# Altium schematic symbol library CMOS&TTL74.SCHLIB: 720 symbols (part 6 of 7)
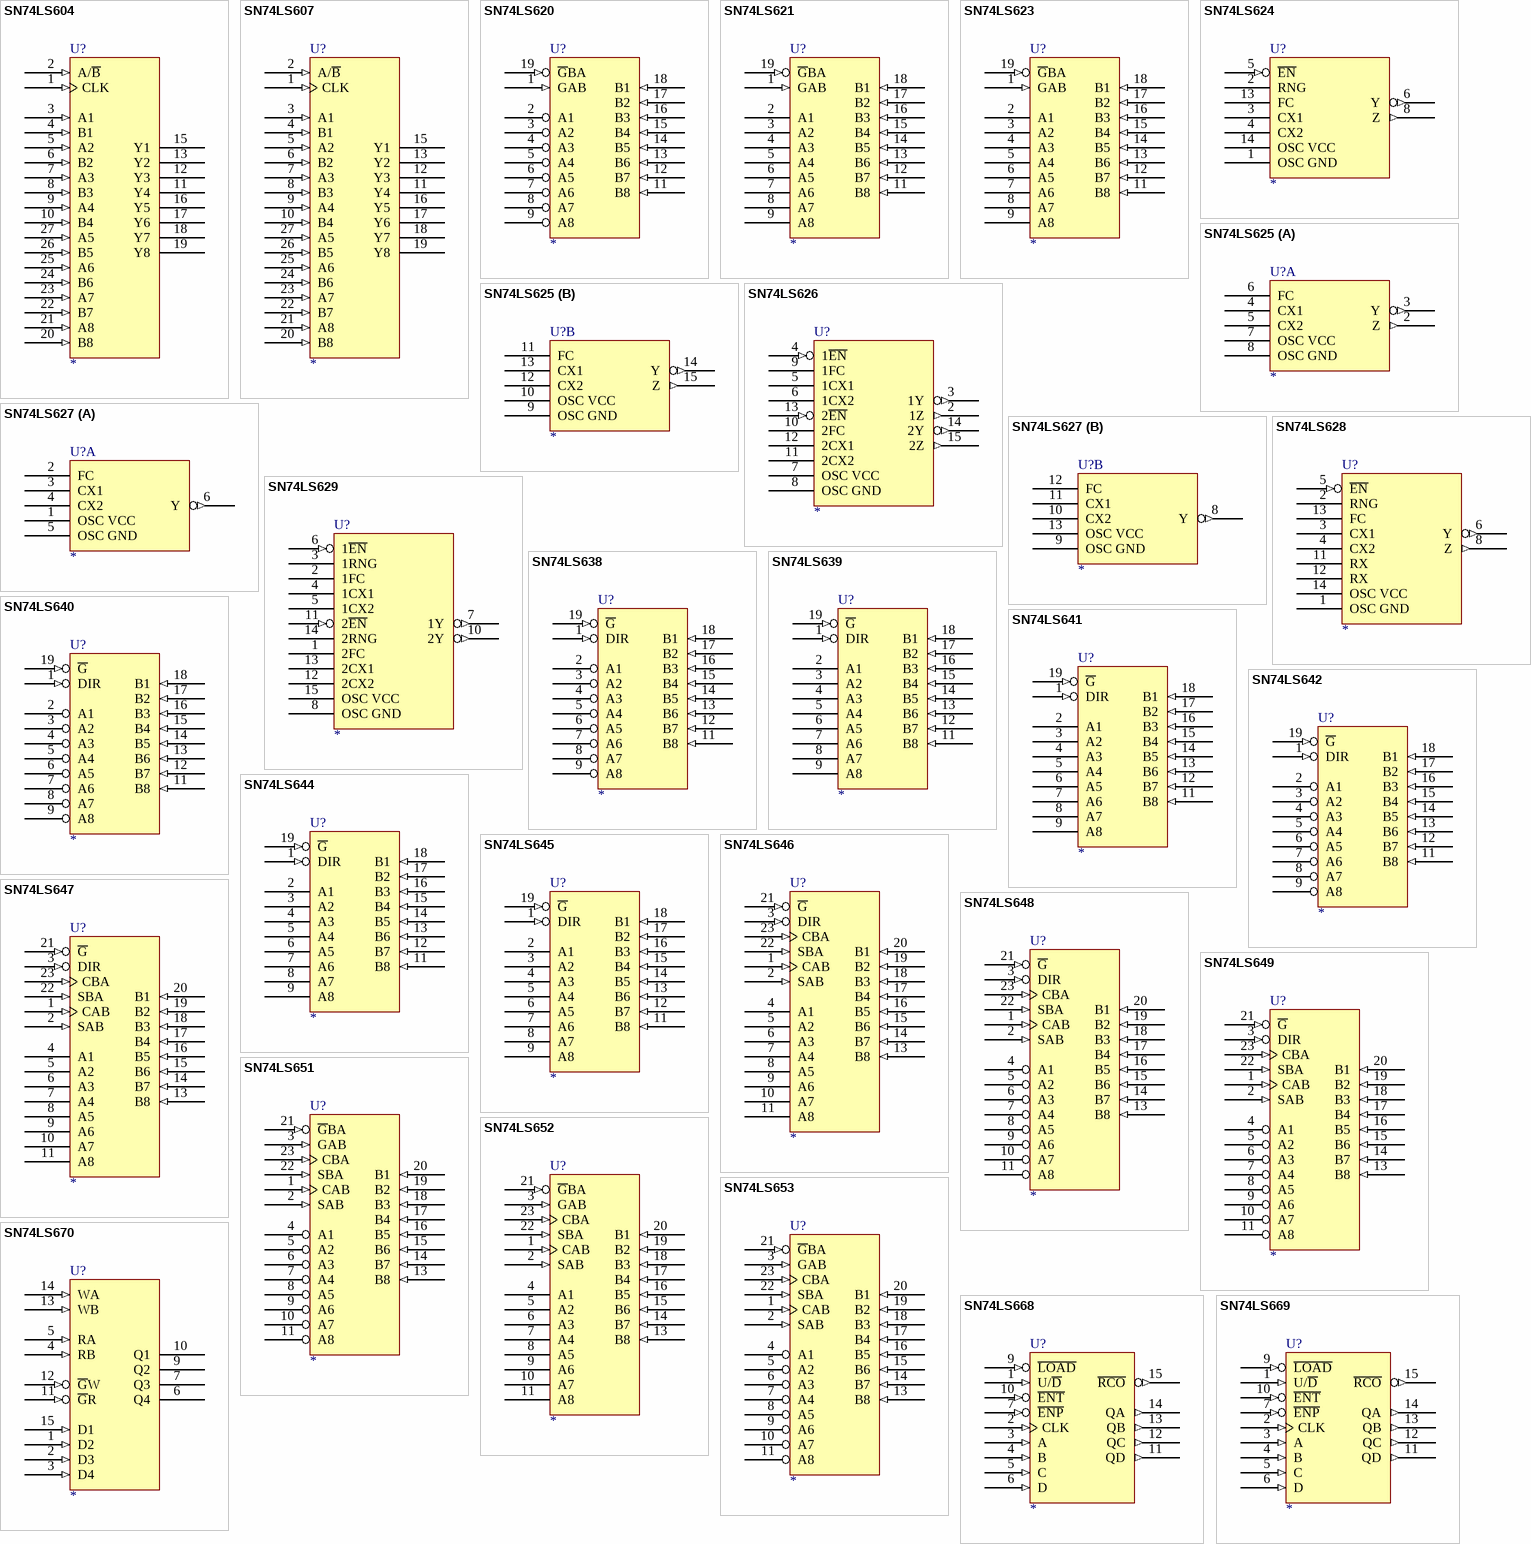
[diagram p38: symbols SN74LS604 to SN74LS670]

## SN74LS629
designator U?
VOLTAGE-CONTROLLED OSC
footprint SO16
footprint DIP-16
pins: 1 2FC, 2 1FC, 3 1RNG, 4 1CX1, 5 1CX2, 6 1~{EN} (in), 7 1Y (out), 8 OSC GND (power), 9 GND (power) hidden to GND, 10 2Y (out), 11 2~{EN} (in), 12 2CX2, 13 2CX1, 14 2RNG, 15 OSC VCC (power), 16 VCC (power) hidden to VCC
1 alternate drawing of the same symbol

## SN74LS638
designator U?
OCTAL BUS TRANCEIVER
footprint DIP-20
footprint SO20W
pins: 1 DIR (in), 2 A1 (oc), 3 A2 (oc), 4 A3 (oc), 5 A4 (oc), 6 A5 (oc), 7 A6 (oc), 8 A7 (oc), 9 A8 (oc), 10 GND (power) hidden to GND, 11 B8 (in), 12 B7 (in), 13 B6 (in), 14 B5 (in), 15 B4 (in), 16 B3 (in), 17 B2 (in), 18 B1 (in), 19 ~{G} (in), 20 VCC (power) hidden to VCC
1 alternate drawing of the same symbol

## SN74LS639
designator U?
OCTAL BUS TRANCEIVER
footprint DIP-20
footprint SO20W
pins: 1 DIR (in), 2 A1 (oc), 3 A2 (oc), 4 A3 (oc), 5 A4 (oc), 6 A5 (oc), 7 A6 (oc), 8 A7 (oc), 9 A8 (oc), 10 GND (power) hidden to GND, 11 B8 (in), 12 B7 (in), 13 B6 (in), 14 B5 (in), 15 B4 (in), 16 B3 (in), 17 B2 (in), 18 B1 (in), 19 ~{G} (in), 20 VCC (power) hidden to VCC
1 alternate drawing of the same symbol

## SN74LS640
designator U?
OCTAL BUS TRANCEIVER
footprint SO20W
footprint DIP-20
pins: 1 DIR (in), 2 A1 (hiz), 3 A2 (hiz), 4 A3 (hiz), 5 A4 (hiz), 6 A5 (hiz), 7 A6 (hiz), 8 A7 (hiz), 9 A8 (hiz), 10 GND (power) hidden to GND, 11 B8 (in), 12 B7 (in), 13 B6 (in), 14 B5 (in), 15 B4 (in), 16 B3 (in), 17 B2 (in), 18 B1 (in), 19 ~{G} (in), 20 VCC (power) hidden to VCC
1 alternate drawing of the same symbol

## SN74LS641
designator U?
OCTAL BUS TRANCEIVER
footprint DIP-20
footprint SO20W
pins: 1 DIR (in), 2 A1 (oc), 3 A2 (oc), 4 A3 (oc), 5 A4 (oc), 6 A5 (oc), 7 A6 (oc), 8 A7 (oc), 9 A8 (oc), 10 GND (power) hidden to GND, 11 B8 (in), 12 B7 (in), 13 B6 (in), 14 B5 (in), 15 B4 (in), 16 B3 (in), 17 B2 (in), 18 B1 (in), 19 ~{G} (in), 20 VCC (power) hidden to VCC
1 alternate drawing of the same symbol

## SN74LS642
designator U?
OCTAL BUS TRANCEIVER
footprint DIP-20
footprint SO20W
pins: 1 DIR (in), 2 A1 (oc), 3 A2 (oc), 4 A3 (oc), 5 A4 (oc), 6 A5 (oc), 7 A6 (oc), 8 A7 (oc), 9 A8 (oc), 10 GND (power) hidden to GND, 11 B8 (in), 12 B7 (in), 13 B6 (in), 14 B5 (in), 15 B4 (in), 16 B3 (in), 17 B2 (in), 18 B1 (in), 19 ~{G} (in), 20 VCC (power) hidden to VCC
1 alternate drawing of the same symbol

## SN74LS644
designator U?
OCTAL BUS TRANCEIVER
footprint DIP-20
footprint SO20W
pins: 1 DIR (in), 2 A1 (oc), 3 A2 (oc), 4 A3 (oc), 5 A4 (oc), 6 A5 (oc), 7 A6 (oc), 8 A7 (oc), 9 A8 (oc), 10 GND (power) hidden to GND, 11 B8 (in), 12 B7 (in), 13 B6 (in), 14 B5 (in), 15 B4 (in), 16 B3 (in), 17 B2 (in), 18 B1 (in), 19 ~{G} (in), 20 VCC (power) hidden to VCC
1 alternate drawing of the same symbol

## SN74LS645
designator U?
OCTAL BUS TRANCEIVER
footprint DIP-20
footprint SO20W
pins: 1 DIR (in), 2 A1 (hiz), 3 A2 (hiz), 4 A3 (hiz), 5 A4 (hiz), 6 A5 (hiz), 7 A6 (hiz), 8 A7 (hiz), 9 A8 (hiz), 10 GND (power) hidden to GND, 11 B8 (in), 12 B7 (in), 13 B6 (in), 14 B5 (in), 15 B4 (in), 16 B3 (in), 17 B2 (in), 18 B1 (in), 19 ~{G} (in), 20 VCC (power) hidden to VCC
1 alternate drawing of the same symbol

## SN74LS646
designator U?
OCTAL BUS TRANCEIVER AND REG
footprint DIP-24
footprint SO24W
pins: 1 CAB (in), 2 SAB (in), 3 DIR (in), 4 A1 (hiz), 5 A2 (hiz), 6 A3 (hiz), 7 A4 (hiz), 8 A5 (hiz), 9 A6 (hiz), 10 A7 (hiz), 11 A8 (hiz), 12 GND (power) hidden to GND, 13 B8 (in), 14 B7 (in), 15 B6 (in), 16 B5 (in), 17 B4 (in), 18 B3 (in), 19 B2 (in), 20 B1 (in), 21 ~{G} (in), 22 SBA (in), 23 CBA (in), 24 VCC (power) hidden to VCC
1 alternate drawing of the same symbol

## SN74LS647
designator U?
OCTAL BUS TRANCEIVER AND REG
footprint DIP-24
footprint SO24W
pins: 1 CAB (in), 2 SAB (in), 3 DIR (in), 4 A1 (oc), 5 A2 (oc), 6 A3 (oc), 7 A4 (oc), 8 A5 (oc), 9 A6 (oc), 10 A7 (oc), 11 A8 (oc), 12 GND (power) hidden to GND, 13 B8 (in), 14 B7 (in), 15 B6 (in), 16 B5 (in), 17 B4 (in), 18 B3 (in), 19 B2 (in), 20 B1 (in), 21 ~{G} (in), 22 SBA (in), 23 CBA (in), 24 VCC (power) hidden to VCC
1 alternate drawing of the same symbol

## SN74LS648
designator U?
OCTAL BUS TRANCEIVER AND REG
footprint DIP-24
footprint SO24W
pins: 1 CAB (in), 2 SAB (in), 3 DIR (in), 4 A1 (hiz), 5 A2 (hiz), 6 A3 (hiz), 7 A4 (hiz), 8 A5 (hiz), 9 A6 (hiz), 10 A7 (hiz), 11 A8 (hiz), 12 GND (power) hidden to GND, 13 B8 (in), 14 B7 (in), 15 B6 (in), 16 B5 (in), 17 B4 (in), 18 B3 (in), 19 B2 (in), 20 B1 (in), 21 ~{G} (in), 22 SBA (in), 23 CBA (in), 24 VCC (power) hidden to VCC
1 alternate drawing of the same symbol

## SN74LS649
designator U?
OCTAL BUS TRANCEIVER AND REG
footprint SO24W
footprint DIP-24
pins: 1 CAB (in), 2 SAB (in), 3 DIR (in), 4 A1 (oc), 5 A2 (oc), 6 A3 (oc), 7 A4 (oc), 8 A5 (oc), 9 A6 (oc), 10 A7 (oc), 11 A8 (oc), 12 GND (power) hidden to GND, 13 B8 (in), 14 B7 (in), 15 B6 (in), 16 B5 (in), 17 B4 (in), 18 B3 (in), 19 B2 (in), 20 B1 (in), 21 ~{G} (in), 22 SBA (in), 23 CBA (in), 24 VCC (power) hidden to VCC
1 alternate drawing of the same symbol

## SN74LS651
designator U?
OCTAL BUS TRANCEIVER AND REG
footprint DIP-24
footprint SO24W
pins: 1 CAB (in), 2 SAB (in), 3 GAB (in), 4 A1 (hiz), 5 A2 (hiz), 6 A3 (hiz), 7 A4 (hiz), 8 A5 (hiz), 9 A6 (hiz), 10 A7 (hiz), 11 A8 (hiz), 12 GND (power) hidden to GND, 13 B8 (in), 14 B7 (in), 15 B6 (in), 16 B5 (in), 17 B4 (in), 18 B3 (in), 19 B2 (in), 20 B1 (in), 21 ~{G}BA (in), 22 SBA (in), 23 CBA (in), 24 VCC (power) hidden to VCC
1 alternate drawing of the same symbol

## SN74LS652
designator U?
OCTAL BUS TRANCEIVER AND REG
footprint SO24W
footprint DIP-24
pins: 1 CAB (in), 2 SAB (in), 3 GAB (in), 4 A1 (hiz), 5 A2 (hiz), 6 A3 (hiz), 7 A4 (hiz), 8 A5 (hiz), 9 A6 (hiz), 10 A7 (hiz), 11 A8 (hiz), 12 GND (power) hidden to GND, 13 B8 (in), 14 B7 (in), 15 B6 (in), 16 B5 (in), 17 B4 (in), 18 B3 (in), 19 B2 (in), 20 B1 (in), 21 ~{G}BA (in), 22 SBA (in), 23 CBA (in), 24 VCC (power) hidden to VCC
1 alternate drawing of the same symbol

## SN74LS653
designator U?
OCTAL BUS TRANCEIVER AND REG
footprint DIP-24
footprint SO24W
pins: 1 CAB (in), 2 SAB (in), 3 GAB (in), 4 A1 (oc), 5 A2 (oc), 6 A3 (oc), 7 A4 (oc), 8 A5 (oc), 9 A6 (oc), 10 A7 (oc), 11 A8 (oc), 12 GND (power) hidden to GND, 13 B8 (in), 14 B7 (in), 15 B6 (in), 16 B5 (in), 17 B4 (in), 18 B3 (in), 19 B2 (in), 20 B1 (in), 21 ~{G}BA (in), 22 SBA (in), 23 CBA (in), 24 VCC (power) hidden to VCC
1 alternate drawing of the same symbol

## SN74LS668
designator U?
SYNCHRONOUS 4-BIT UP/DOWN CNT
footprint DIP-16
footprint SO16
pins: 1 U/~{D} (in), 2 CLK (in), 3 A (in), 4 B (in), 5 C (in), 6 D (in), 7 ~{ENP} (in), 8 GND (power) hidden to GND, 9 ~{LOAD} (in), 10 ~{ENT} (in), 11 QD (out), 12 QC (out), 13 QB (out), 14 QA (out), 15 ~{RCO} (out), 16 VCC (power) hidden to VCC
1 alternate drawing of the same symbol

## SN74LS669
designator U?
SYNCHRONOUS 4-BIT UP/DOWN CNT
footprint DIP-16
footprint SO16
pins: 1 U/~{D} (in), 2 CLK (in), 3 A (in), 4 B (in), 5 C (in), 6 D (in), 7 ~{ENP} (in), 8 GND (power) hidden to GND, 9 ~{LOAD} (in), 10 ~{ENT} (in), 11 QD (out), 12 QC (out), 13 QB (out), 14 QA (out), 15 ~{RCO} (out), 16 VCC (power) hidden to VCC
1 alternate drawing of the same symbol

## SN74LS670
designator U?
4-BY-4 REG FILES 3SO
footprint SO16
footprint DIP-16
pins: 1 D2 (in), 2 D3 (in), 3 D4 (in), 4 RB (in), 5 RA (in), 6 Q4 (hiz), 7 Q3 (hiz), 8 GND (power) hidden to GND, 9 Q2 (hiz), 10 Q1 (hiz), 11 ~{G}R (in), 12 ~{G}W (in), 13 WB (in), 14 WA (in), 15 D1 (in), 16 VCC (power) hidden to VCC
1 alternate drawing of the same symbol

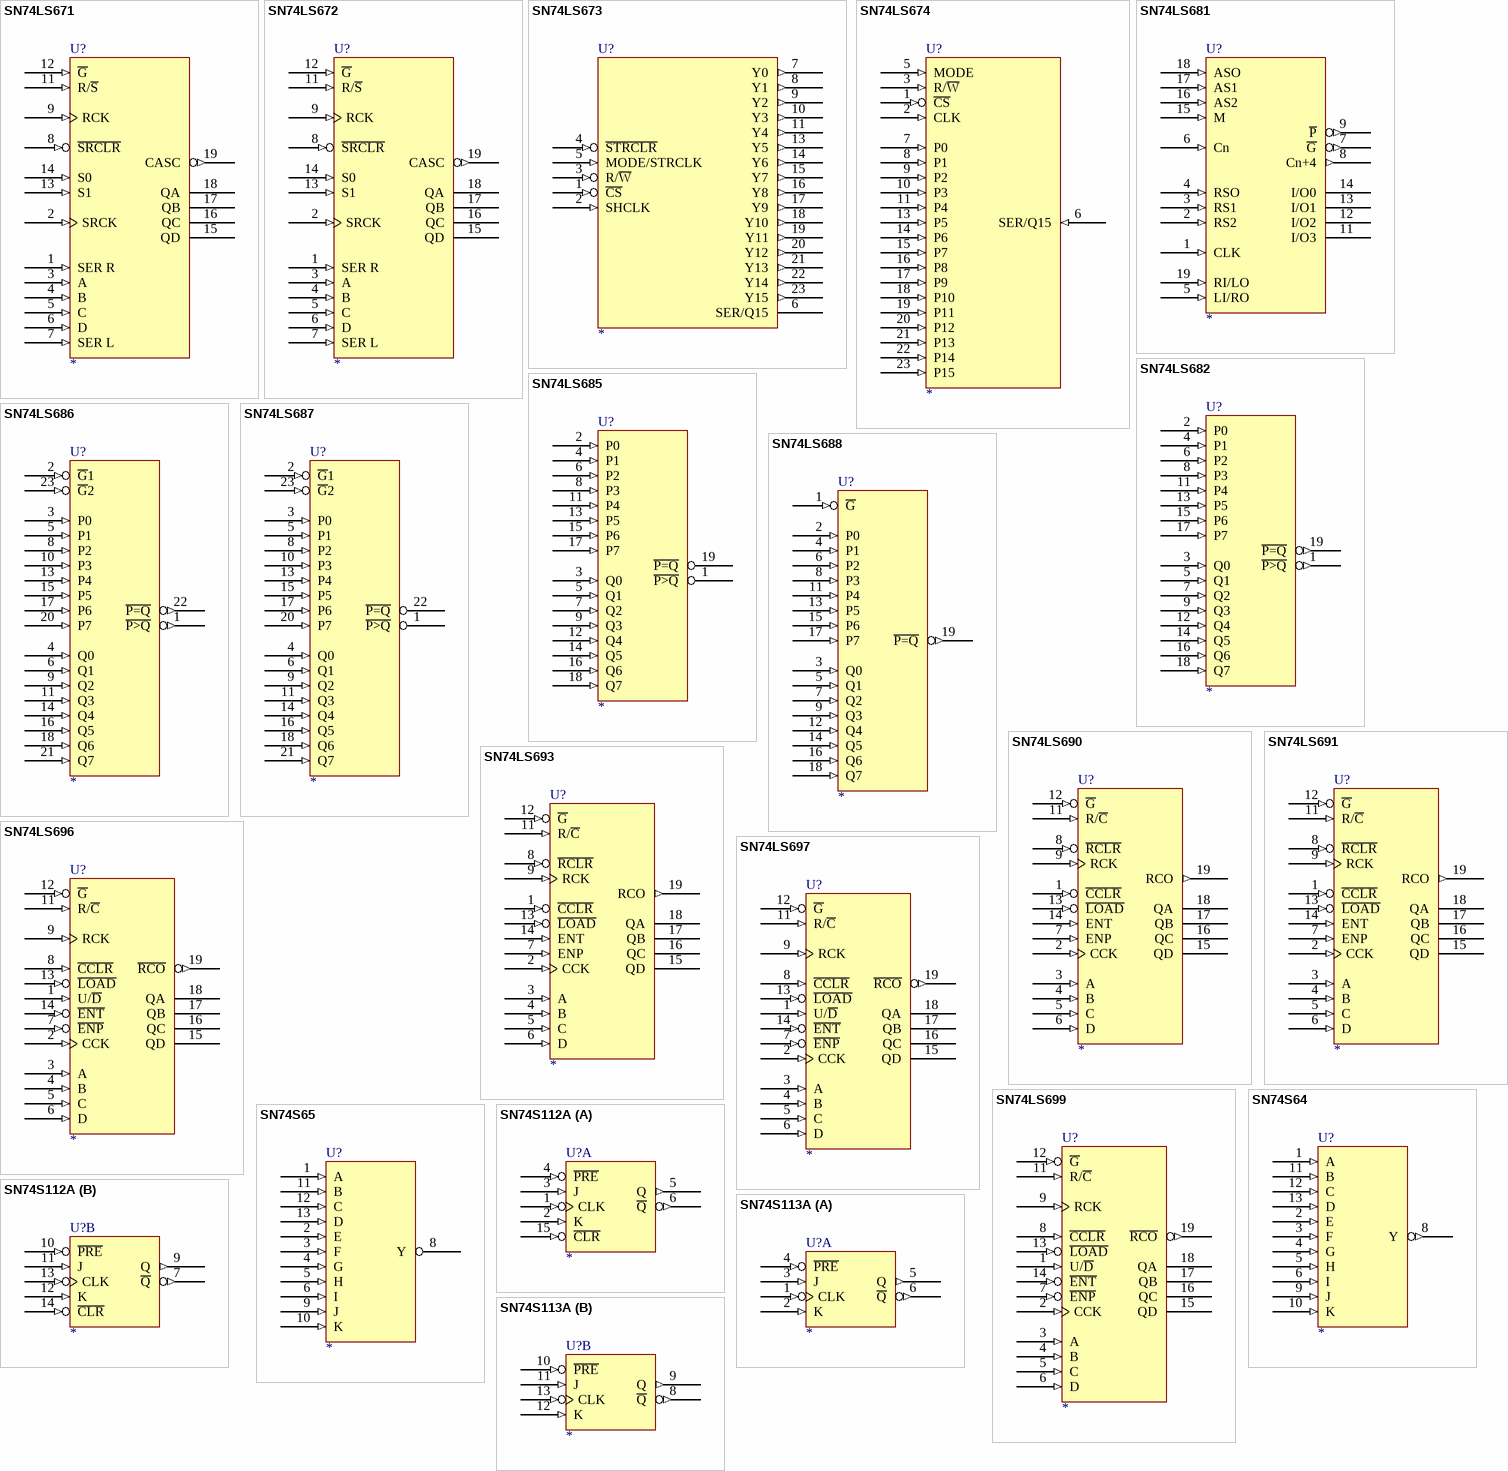
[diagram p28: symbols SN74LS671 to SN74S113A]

## SN74LS671
designator U?
4-BIT UNIVERSAL SFT REG/LCH 3SO
footprint SO20W
footprint DIP-20
pins: 1 SER R (in), 2 SRCK (in), 3 A (in), 4 B (in), 5 C (in), 6 D (in), 7 SER L (in), 8 ~{SRCLR} (in), 9 RCK (in), 10 GND (power) hidden to GND, 11 R/~{S} (in), 12 ~{G} (in), 13 S1 (in), 14 S0 (in), 15 QD (hiz), 16 QC (hiz), 17 QB (hiz), 18 QA (hiz), 19 CASC (out), 20 VCC (power) hidden to VCC
1 alternate drawing of the same symbol

## SN74LS672
designator U?
4-BIT UNIVERSAL SFT REG/LCH 3SO
footprint SO20W
footprint DIP-20
pins: 1 SER R (in), 2 SRCK (in), 3 A (in), 4 B (in), 5 C (in), 6 D (in), 7 SER L (in), 8 ~{SRCLR} (in), 9 RCK (in), 10 GND (power) hidden to GND, 11 R/~{S} (in), 12 ~{G} (in), 13 S1 (in), 14 S0 (in), 15 QD (hiz), 16 QC (hiz), 17 QB (hiz), 18 QA (hiz), 19 CASC (out), 20 VCC (power) hidden to VCC
1 alternate drawing of the same symbol

## SN74LS673
designator U?
16-BIT SFT REG
footprint SO24W
footprint DIP-24
pins: 1 ~{CS} (in), 2 SHCLK (in), 3 R/~{W} (in), 4 ~{STRCLR} (in), 5 MODE/STRCLK (in), 6 SER/Q15 (hiz), 7 Y0 (out), 8 Y1 (out), 9 Y2 (out), 10 Y3 (out), 11 Y4 (out), 12 GND (power) hidden to GND, 13 Y5 (out), 14 Y6 (out), 15 Y7 (out), 16 Y8 (out), 17 Y9 (out), 18 Y10 (out), 19 Y11 (out), 20 Y12 (out), 21 Y13 (out), 22 Y14 (out), 23 Y15 (out), 24 VCC (power) hidden to VCC
1 alternate drawing of the same symbol

## SN74LS674
designator U?
16-BIT SFT REG
footprint SO24W
footprint DIP-24
pins: 1 ~{CS} (in), 2 CLK (in), 3 R/~{W} (in), 5 MODE (in), 6 SER/Q15 (in), 7 P0 (in), 8 P1 (in), 9 P2 (in), 10 P3 (in), 11 P4 (in), 12 GND (power) hidden to GND, 13 P5 (in), 14 P6 (in), 15 P7 (in), 16 P8 (in), 17 P9 (in), 18 P10 (in), 19 P11 (in), 20 P12 (in), 21 P13 (in), 22 P14 (in), 23 P15 (in), 24 VCC (power) hidden to VCC
1 alternate drawing of the same symbol

## SN74LS681
designator U?
4-BIT PARALLEL BIN ACCUMULATOR
footprint DIP-20
footprint SO20W
pins: 1 CLK (in), 2 RS2 (in), 3 RS1 (in), 4 RSO (in), 5 LI/RO (in), 6 Cn (in), 7 ~{G} (out), 8 Cn+4 (out), 9 ~{P} (out), 10 GND (power) hidden to GND, 11 I/O3 (hiz), 12 I/O2 (hiz), 13 I/O1 (hiz), 14 I/O0 (hiz), 15 M (in), 16 AS2 (in), 17 AS1 (in), 18 ASO (in), 19 RI/LO (in), 20 VCC (power) hidden to VCC
1 alternate drawing of the same symbol

## SN74LS682
designator U?
8-BIT MAGNITUDE/IDENTITY COMPARATOR
footprint DIP-20
footprint SO20W
pins: 1 ~{P>Q} (out), 2 P0 (in), 3 Q0 (in), 4 P1 (in), 5 Q1 (in), 6 P2 (in), 7 Q2 (in), 8 P3 (in), 9 Q3 (in), 10 GND (power) hidden to GND, 11 P4 (in), 12 Q4 (in), 13 P5 (in), 14 Q5 (in), 15 P6 (in), 16 Q6 (in), 17 P7 (in), 18 Q7 (in), 19 ~{P=Q} (out), 20 VCC (power) hidden to VCC
1 alternate drawing of the same symbol

## SN74LS685
designator U?
8-BIT MAGNITUDE/IDENTITY COMPARATOR
footprint SO20W
footprint DIP-20
pins: 1 ~{P>Q} (oc), 2 P0 (in), 3 Q0 (in), 4 P1 (in), 5 Q1 (in), 6 P2 (in), 7 Q2 (in), 8 P3 (in), 9 Q3 (in), 10 GND (power) hidden to GND, 11 P4 (in), 12 Q4 (in), 13 P5 (in), 14 Q5 (in), 15 P6 (in), 16 Q6 (in), 17 P7 (in), 18 Q7 (in), 19 ~{P=Q} (oc), 20 VCC (power) hidden to VCC
1 alternate drawing of the same symbol

## SN74LS686
designator U?
8-BIT MAGNITUDE/IDENTITY COMPARATOR
footprint DIP-24
footprint SO24W
pins: 1 ~{P>Q} (out), 2 ~{G}1 (in), 3 P0 (in), 4 Q0 (in), 5 P1 (in), 6 Q1 (in), 8 P2 (in), 9 Q2 (in), 10 P3 (in), 11 Q3 (in), 12 GND (power) hidden to GND, 13 P4 (in), 14 Q4 (in), 15 P5 (in), 16 Q5 (in), 17 P6 (in), 18 Q6 (in), 20 P7 (in), 21 Q7 (in), 22 ~{P=Q} (out), 23 ~{G}2 (in), 24 VCC (power) hidden to VCC
1 alternate drawing of the same symbol

## SN74LS687
designator U?
8-BIT MAGNITUDE/IDENTITY COMPARATOR
footprint DIP-24
footprint SO24W
pins: 1 ~{P>Q} (oc), 2 ~{G}1 (in), 3 P0 (in), 4 Q0 (in), 5 P1 (in), 6 Q1 (in), 8 P2 (in), 9 Q2 (in), 10 P3 (in), 11 Q3 (in), 12 GND (power) hidden to GND, 13 P4 (in), 14 Q4 (in), 15 P5 (in), 16 Q5 (in), 17 P6 (in), 18 Q6 (in), 20 P7 (in), 21 Q7 (in), 22 ~{P=Q} (oc), 23 ~{G}2 (in), 24 VCC (power) hidden to VCC
1 alternate drawing of the same symbol

## SN74LS688
designator U?
8-BIT MAGNITUDE/IDENTITY COMPARATOR
footprint DIP-20
footprint SO20W
pins: 1 ~{G} (in), 2 P0 (in), 3 Q0 (in), 4 P1 (in), 5 Q1 (in), 6 P2 (in), 7 Q2 (in), 8 P3 (in), 9 Q3 (in), 10 GND (power) hidden to GND, 11 P4 (in), 12 Q4 (in), 13 P5 (in), 14 Q5 (in), 15 P6 (in), 16 Q6 (in), 17 P7 (in), 18 Q7 (in), 19 ~{P=Q} (out), 20 VCC (power) hidden to VCC
1 alternate drawing of the same symbol

## SN74LS690
designator U?
SYNCHRONOUS CNT WITH OUTPUT REG AND MUX 3SO
footprint SO20W
footprint DIP-20
pins: 1 ~{CCLR} (in), 2 CCK (in), 3 A (in), 4 B (in), 5 C (in), 6 D (in), 7 ENP (in), 8 ~{RCLR} (in), 9 RCK (in), 10 GND (power) hidden to GND, 11 R/~{C} (in), 12 ~{G} (in), 13 ~{LOAD} (in), 14 ENT (in), 15 QD (hiz), 16 QC (hiz), 17 QB (hiz), 18 QA (hiz), 19 RCO (out), 20 VCC (power) hidden to VCC
1 alternate drawing of the same symbol

## SN74LS691
designator U?
SYNCHRONOUS CNT WITH OUTPUT REG AND MUX 3SO
footprint SO20W
footprint DIP-20
pins: 1 ~{CCLR} (in), 2 CCK (in), 3 A (in), 4 B (in), 5 C (in), 6 D (in), 7 ENP (in), 8 ~{RCLR} (in), 9 RCK (in), 10 GND (power) hidden to GND, 11 R/~{C} (in), 12 ~{G} (in), 13 ~{LOAD} (in), 14 ENT (in), 15 QD (hiz), 16 QC (hiz), 17 QB (hiz), 18 QA (hiz), 19 RCO (out), 20 VCC (power) hidden to VCC
1 alternate drawing of the same symbol

## SN74LS693
designator U?
SYNCHRONOUS CNT WITH OUTPUT REG AND MUX 3SO
footprint DIP-20
footprint SO20W
pins: 1 ~{CCLR} (in), 2 CCK (in), 3 A (in), 4 B (in), 5 C (in), 6 D (in), 7 ENP (in), 8 ~{RCLR} (in), 9 RCK (in), 10 GND (power) hidden to GND, 11 R/~{C} (in), 12 ~{G} (in), 13 ~{LOAD} (in), 14 ENT (in), 15 QD (hiz), 16 QC (hiz), 17 QB (hiz), 18 QA (hiz), 19 RCO (out), 20 VCC (power) hidden to VCC
1 alternate drawing of the same symbol

## SN74LS696
designator U?
SYNCHRONOUS U/D CNT WITH OUTPUT REG AND MUX 3SO
footprint DIP-20
footprint SO20W
pins: 1 U/~{D} (in), 2 CCK (in), 3 A (in), 4 B (in), 5 C (in), 6 D (in), 7 ~{ENP} (in), 8 ~{CCLR} (in), 9 RCK (in), 10 GND (power) hidden to GND, 11 R/~{C} (in), 12 ~{G} (in), 13 ~{LOAD} (in), 14 ~{ENT} (in), 15 QD (hiz), 16 QC (hiz), 17 QB (hiz), 18 QA (hiz), 19 ~{RCO} (out), 20 VCC (power) hidden to VCC
1 alternate drawing of the same symbol

## SN74LS697
designator U?
SYNCHRONOUS U/D CNT WITH OUTPUT REG AND MUX 3SO
footprint DIP-20
footprint SO20W
pins: 1 U/~{D} (in), 2 CCK (in), 3 A (in), 4 B (in), 5 C (in), 6 D (in), 7 ~{ENP} (in), 8 ~{CCLR} (in), 9 RCK (in), 10 GND (power) hidden to GND, 11 R/~{C} (in), 12 ~{G} (in), 13 ~{LOAD} (in), 14 ~{ENT} (in), 15 QD (hiz), 16 QC (hiz), 17 QB (hiz), 18 QA (hiz), 19 ~{RCO} (out), 20 VCC (power) hidden to VCC
1 alternate drawing of the same symbol

## SN74LS699
designator U?
SYNCHRONOUS U/D CNT WITH OUTPUT REG AND MUX 3SO
footprint DIP-20
footprint SO20W
pins: 1 U/~{D} (in), 2 CCK (in), 3 A (in), 4 B (in), 5 C (in), 6 D (in), 7 ~{ENP} (in), 8 ~{CCLR} (in), 9 RCK (in), 10 GND (power) hidden to GND, 11 R/~{C} (in), 12 ~{G} (in), 13 ~{LOAD} (in), 14 ~{ENT} (in), 15 QD (hiz), 16 QC (hiz), 17 QB (hiz), 18 QA (hiz), 19 ~{RCO} (out), 20 VCC (power) hidden to VCC
1 alternate drawing of the same symbol

## SN74S64
designator U?
4-2-3-2 IN AND-OR-INVERT G
footprint SO14
footprint DIP-14
pins: 1 A (in), 2 E (in), 3 F (in), 4 G (in), 5 H (in), 6 I (in), 7 GND (power) hidden to GND, 8 Y (out), 9 J (in), 10 K (in), 11 B (in), 12 C (in), 13 D (in), 14 VCC (power) hidden to VCC
1 alternate drawing of the same symbol

## SN74S65
designator U?
4-2-3-2 IN AND-OR-INVERT G
footprint SO14
footprint DIP-14
pins: 1 A (in), 2 E (in), 3 F (in), 4 G (in), 5 H (in), 6 I (in), 7 GND (power) hidden to GND, 8 Y (oc), 9 J (in), 10 K (in), 11 B (in), 12 C (in), 13 D (in), 14 VCC (power) hidden to VCC
1 alternate drawing of the same symbol

## SN74S112A
designator U?
DUAL J-K NET FF RS CR
footprint SO16
footprint DIP-16
part A pins: 1 CLK (in), 2 K (in), 3 J (in), 4 ~{PRE} (in), 5 Q (out), 6 ~{Q} (out), 8 GND (power) hidden to GND, 15 ~{CLR} (in), 16 VCC (power) hidden to VCC
part B pins: 7 ~{Q} (out), 8 GND (power) hidden to GND, 9 Q (out), 10 ~{PRE} (in), 11 J (in), 12 K (in), 13 CLK (in), 14 ~{CLR} (in), 16 VCC (power) hidden to VCC
1 alternate drawing of the same symbol

## SN74S113A
designator U?
DUAL J-K NET FF RS
footprint SO14
footprint DIP-14
part A pins: 1 CLK (in), 2 K (in), 3 J (in), 4 ~{PRE} (in), 5 Q (out), 6 ~{Q} (out), 7 GND (power) hidden to GND, 14 VCC (power) hidden to VCC
part B pins: 7 GND (power) hidden to GND, 8 ~{Q} (out), 9 Q (out), 10 ~{PRE} (in), 11 J (in), 12 K (in), 13 CLK (in), 14 VCC (power) hidden to VCC
1 alternate drawing of the same symbol

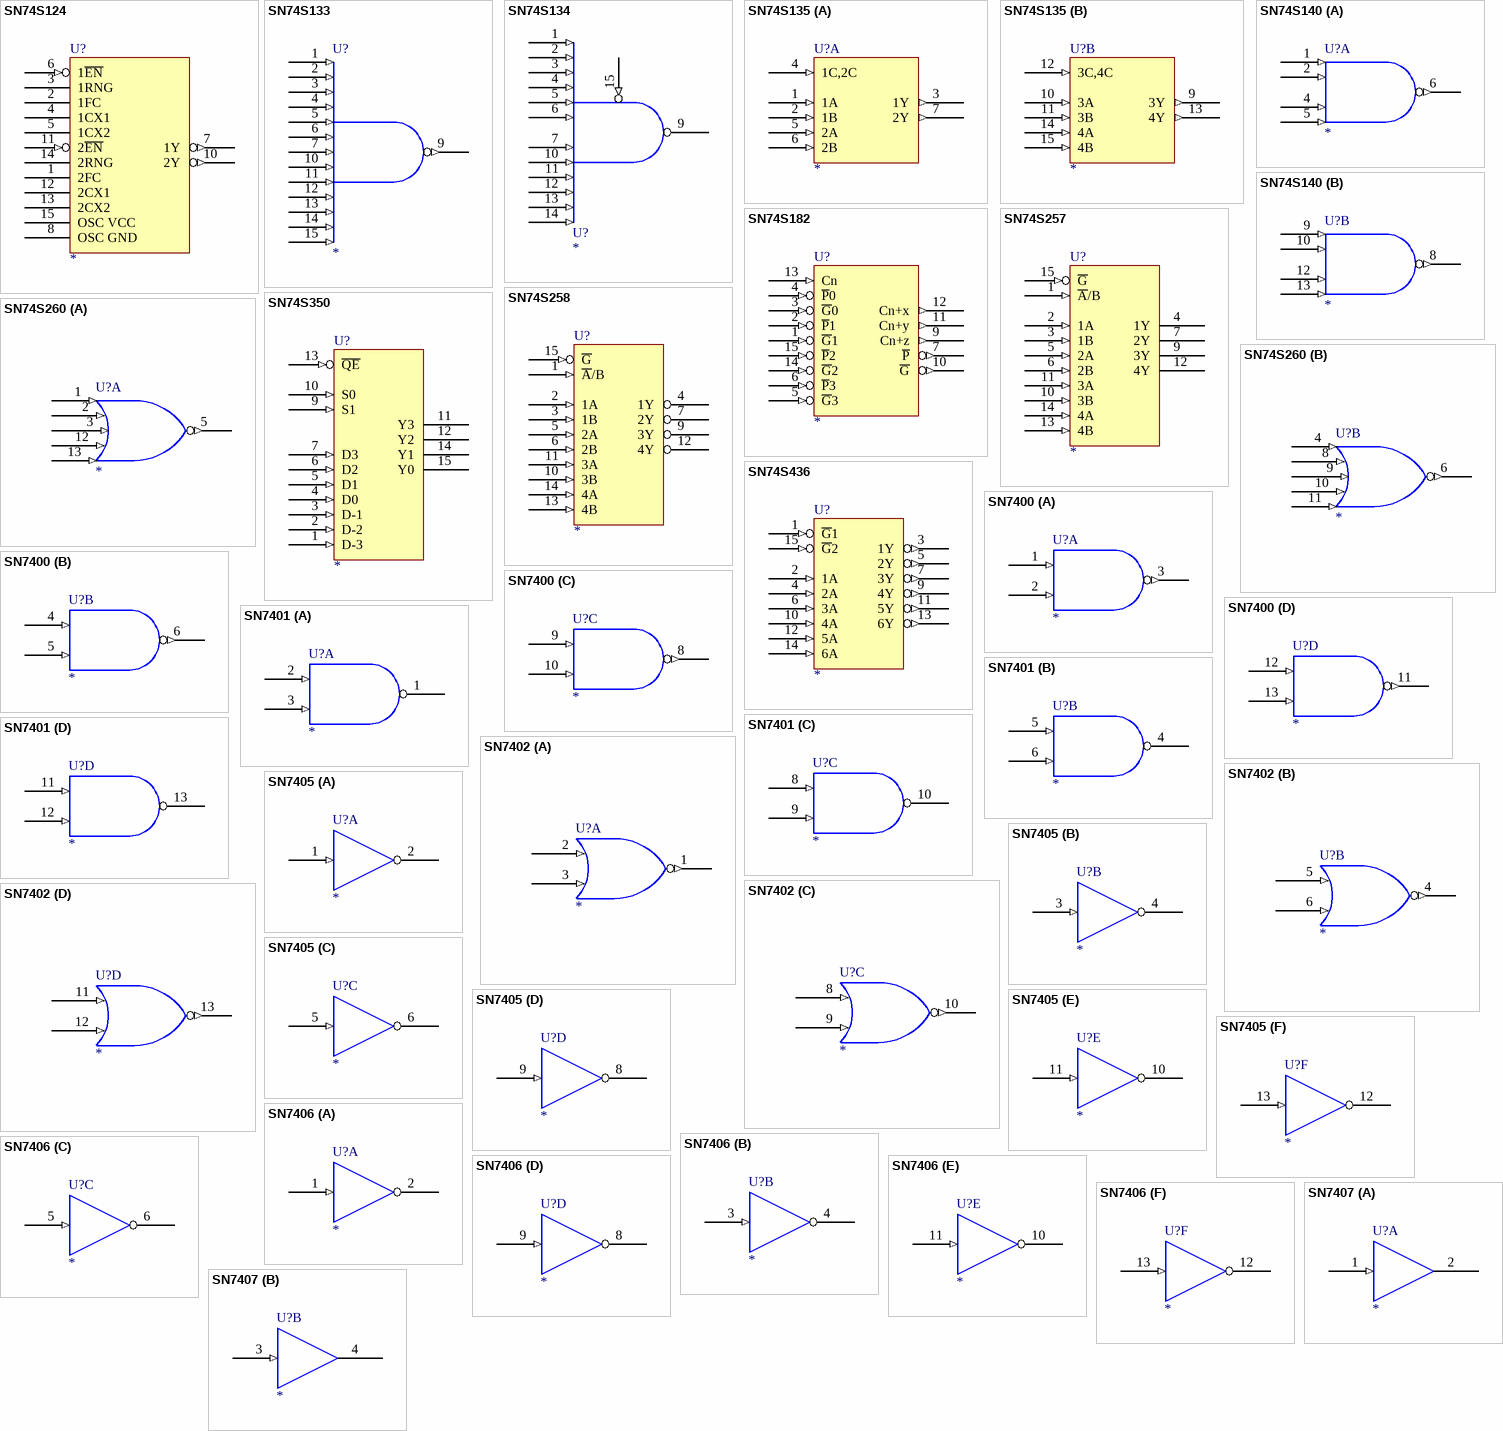
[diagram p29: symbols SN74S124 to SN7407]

## SN74S124
designator U?
DUAL VOLTAGE-CONTROLLED OSC
footprint SO16
footprint DIP-16
pins: 1 2FC, 2 1FC, 3 1RNG, 4 1CX1, 5 1CX2, 6 1~{EN} (in), 7 1Y (out), 8 OSC GND (power), 9 GND (power) hidden to GND, 10 2Y (out), 11 2~{EN} (in), 12 2CX1, 13 2CX2, 14 2RNG, 15 OSC VCC (power), 16 VCC (power) hidden to VCC
1 alternate drawing of the same symbol

## SN74S133
designator U?
13-IN POS Nand G
footprint SO16
footprint DIP-16
pins: 1 (in), 2 (in), 3 (in), 4 (in), 5 (in), 6 (in), 7 (in), 8 GND (power) hidden to GND, 9 (out), 10 (in), 11 (in), 12 (in), 13 (in), 14 (in), 15 (in), 16 VCC (power) hidden to VCC
2 alternate drawings of the same symbol

## SN74S134
designator U?
12-IN POS Nand G 3SO
footprint SO16
footprint DIP-16
pins: 1 (in), 2 (in), 3 (in), 4 (in), 5 (in), 6 (in), 7 (in), 8 GND (power) hidden to GND, 9 (hiz), 10 (in), 11 (in), 12 (in), 13 (in), 14 (in), 15 (in), 16 VCC (power) hidden to VCC
2 alternate drawings of the same symbol

## SN74S135
designator U?
QUAD XOR/NOR G
footprint SO16
footprint DIP-16
part A pins: 1 1A (in), 2 1B (in), 3 1Y (out), 4 1C,2C (in), 5 2A (in), 6 2B (in), 7 2Y (out), 8 GND (power) hidden to GND, 16 VCC (power) hidden to VCC
part B pins: 8 GND (power) hidden to GND, 9 3Y (out), 10 3A (in), 11 3B (in), 12 3C,4C (in), 13 4Y (out), 14 4A (in), 15 4B (in), 16 VCC (power) hidden to VCC
1 alternate drawing of the same symbol

## SN74S140
designator U?
Dual 4-in Pos Nand 50-OHM LINE DRV
footprint SO14
footprint DIP-14
part A pins: 1 (in), 2 (in), 4 (in), 5 (in), 6 (out), 7 GND (power) hidden to GND, 14 VCC (power) hidden to VCC
part B pins: 7 GND (power) hidden to GND, 8 (out), 9 (in), 10 (in), 12 (in), 13 (in), 14 VCC (power) hidden to VCC
2 alternate drawings of the same symbol

## SN74S182
designator U?
LOOK-AHEAD CARRY GNR
footprint SO16
footprint DIP-16
pins: 1 ~{G}1 (in), 2 ~{P}1 (in), 3 ~{G}0 (in), 4 ~{P}0 (in), 5 ~{G}3 (in), 6 ~{P}3 (in), 7 ~{P} (out), 8 GND (power) hidden to GND, 9 Cn+z (out), 10 ~{G} (out), 11 Cn+y (out), 12 Cn+x (out), 13 Cn (in), 14 ~{G}2 (in), 15 ~{P}2 (in), 16 VCC (power) hidden to VCC
1 alternate drawing of the same symbol

## SN74S257
designator U?
QUAD 2-1LINE DATA SLCR/MUX
footprint SO16
footprint DIP-16
pins: 1 ~{A}/B (in), 2 1A (in), 3 1B (in), 4 1Y (hiz), 5 2A (in), 6 2B (in), 7 2Y (hiz), 8 GND (power) hidden to GND, 9 3Y (hiz), 10 3B (in), 11 3A (in), 12 4Y (hiz), 13 4B (in), 14 4A (in), 15 ~{G} (in), 16 VCC (power) hidden to VCC
1 alternate drawing of the same symbol

## SN74S258
designator U?
QUAD 2-1LINE DATA SLCR/MUX
footprint SO16
footprint DIP-16
pins: 1 ~{A}/B (in), 2 1A (in), 3 1B (in), 4 1Y (hiz), 5 2A (in), 6 2B (in), 7 2Y (hiz), 8 GND (power) hidden to GND, 9 3Y (hiz), 10 3B (in), 11 3A (in), 12 4Y (hiz), 13 4B (in), 14 4A (in), 15 ~{G} (in), 16 VCC (power) hidden to VCC
1 alternate drawing of the same symbol

## SN74S260
designator U?
DUAL 5-IN POS NOR G
footprint SO14
footprint DIP-14
part A pins: 1 (in), 2 (in), 3 (in), 5 (out), 7 GND (power) hidden to GND, 12 (in), 13 (in), 14 VCC (power) hidden to VCC
part B pins: 4 (in), 6 (out), 7 GND (power) hidden to GND, 8 (in), 9 (in), 10 (in), 11 (in), 14 VCC (power) hidden to VCC
2 alternate drawings of the same symbol

## SN74S350
designator U?
4-BIT SHIFTER 3SO
footprint SO16
footprint DIP-16
pins: 1 D-3 (in), 2 D-2 (in), 3 D-1 (in), 4 D0 (in), 5 D1 (in), 6 D2 (in), 7 D3 (in), 8 GND (power) hidden to GND, 9 S1 (in), 10 S0 (in), 11 Y3 (hiz), 12 Y2 (hiz), 13 ~{QE} (in), 14 Y1 (hiz), 15 Y0 (hiz), 16 VCC (power) hidden to VCC
1 alternate drawing of the same symbol

## SN74S436
designator U?
LINE DRV/MEMORY DRV CCT
footprint SO16
footprint DIP-16
pins: 1 ~{G}1 (in), 2 1A (in), 3 1Y (out), 4 2A (in), 5 2Y (out), 6 3A (in), 7 3Y (out), 8 GND (power) hidden to GND, 9 4Y (out), 10 4A (in), 11 5Y (out), 12 5A (in), 13 6Y (out), 14 6A (in), 15 ~{G}2 (in), 16 VCC (power) hidden to VCC
1 alternate drawing of the same symbol

## SN7400
designator U?
Quad 2-IN Pos Nand G
footprint DIP-14
footprint SO14
part A pins: 1 (in), 2 (in), 3 (out), 7 GND (power) hidden to GND, 14 VCC (power) hidden to VCC
part B pins: 4 (in), 5 (in), 6 (out), 7 GND (power) hidden to GND, 14 VCC (power) hidden to VCC
part C pins: 7 GND (power) hidden to GND, 8 (out), 9 (in), 10 (in), 14 VCC (power) hidden to VCC
part D pins: 7 GND (power) hidden to GND, 11 (out), 12 (in), 13 (in), 14 VCC (power) hidden to VCC
2 alternate drawings of the same symbol

## SN7401
designator U?
Quad 2-IN Pos Nand G OCO
footprint DIP-14
footprint SO14
part A pins: 1 (oc), 2 (in), 3 (in), 7 GND (power) hidden to GND, 14 VCC (power) hidden to VCC
part B pins: 4 (oc), 5 (in), 6 (in), 7 GND (power) hidden to GND, 14 VCC (power) hidden to VCC
part C pins: 7 GND (power) hidden to GND, 8 (in), 9 (in), 10 (oc), 14 VCC (power) hidden to VCC
part D pins: 7 GND (power) hidden to GND, 11 (in), 12 (in), 13 (oc), 14 VCC (power) hidden to VCC
2 alternate drawings of the same symbol

## SN7402
designator U?
Quad 2-IN Pos Nor G
footprint DIP-14
footprint SO14
part A pins: 1 (out), 2 (in), 3 (in), 7 GND (power) hidden to GND, 14 VCC (power) hidden to VCC
part B pins: 4 (out), 5 (in), 6 (in), 7 GND (power) hidden to GND, 14 VCC (power) hidden to VCC
part C pins: 7 GND (power) hidden to GND, 8 (in), 9 (in), 10 (out), 14 VCC (power) hidden to VCC
part D pins: 7 GND (power) hidden to GND, 11 (in), 12 (in), 13 (out), 14 VCC (power) hidden to VCC
2 alternate drawings of the same symbol

## SN7405
designator U?
Hex Inverters OCO
footprint DIP-14
footprint SO14
part A pins: 1 (in), 2 (oc), 7 GND (power) hidden to GND, 14 VCC (power) hidden to VCC
part B pins: 3 (in), 4 (oc), 7 GND (power) hidden to GND, 14 VCC (power) hidden to VCC
part C pins: 5 (in), 6 (oc), 7 GND (power) hidden to GND, 14 VCC (power) hidden to VCC
part D pins: 7 GND (power) hidden to GND, 8 (oc), 9 (in), 14 VCC (power) hidden to VCC
part E pins: 7 GND (power) hidden to GND, 10 (oc), 11 (in), 14 VCC (power) hidden to VCC
part F pins: 7 GND (power) hidden to GND, 12 (oc), 13 (in), 14 VCC (power) hidden to VCC
2 alternate drawings of the same symbol

## SN7406
designator U?
Hex Inverters Buf/Drv OCO HVO
footprint DIP-14
part A pins: 1 (in), 2 (oc), 7 GND (power) hidden to GND, 14 VCC (power) hidden to VCC
part B pins: 3 (in), 4 (oc), 7 GND (power) hidden to GND, 14 VCC (power) hidden to VCC
part C pins: 5 (in), 6 (oc), 7 GND (power) hidden to GND, 14 VCC (power) hidden to VCC
part D pins: 7 GND (power) hidden to GND, 8 (oc), 9 (in), 14 VCC (power) hidden to VCC
part E pins: 7 GND (power) hidden to GND, 10 (oc), 11 (in), 14 VCC (power) hidden to VCC
part F pins: 7 GND (power) hidden to GND, 12 (oc), 13 (in), 14 VCC (power) hidden to VCC
2 alternate drawings of the same symbol

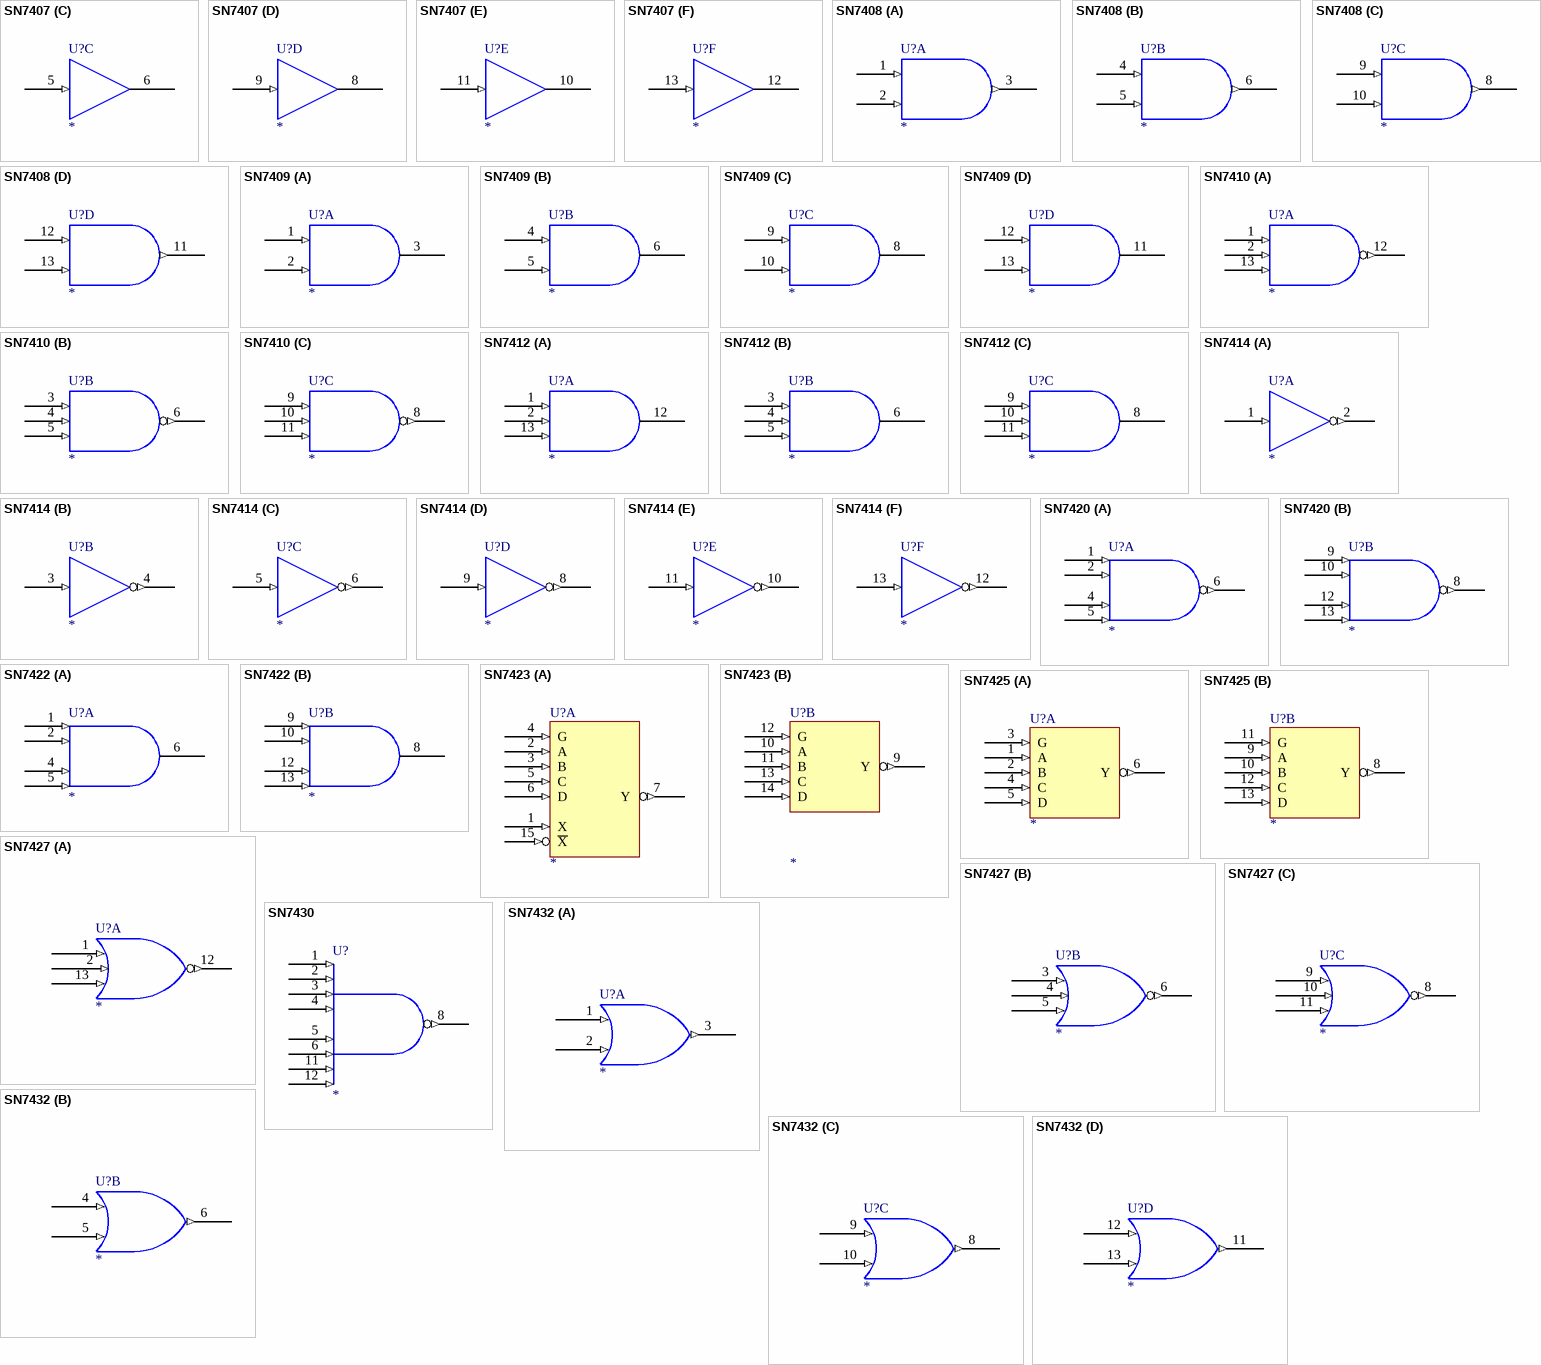
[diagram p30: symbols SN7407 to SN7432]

## SN7407
designator U?
Hex Buf/Drv OCO HVO
footprint DIP-14
part A pins: 1 (in), 2 (oc), 7 GND (power) hidden to GND, 14 VCC (power) hidden to VCC
part B pins: 3 (in), 4 (oc), 7 GND (power) hidden to GND, 14 VCC (power) hidden to VCC
part C pins: 5 (in), 6 (oc), 7 GND (power) hidden to GND, 14 VCC (power) hidden to VCC
part D pins: 7 GND (power) hidden to GND, 8 (oc), 9 (in), 14 VCC (power) hidden to VCC
part E pins: 7 GND (power) hidden to GND, 10 (oc), 11 (in), 14 VCC (power) hidden to VCC
part F pins: 7 GND (power) hidden to GND, 12 (oc), 13 (in), 14 VCC (power) hidden to VCC
2 alternate drawings of the same symbol

## SN7408
designator U?
Quad 2-IN Pos And G
footprint DIP-14
footprint SO14
part A pins: 1 (in), 2 (in), 3 (out), 7 GND (power) hidden to GND, 14 VCC (power) hidden to VCC
part B pins: 4 (in), 5 (in), 6 (out), 7 GND (power) hidden to GND, 14 VCC (power) hidden to VCC
part C pins: 7 GND (power) hidden to GND, 8 (out), 9 (in), 10 (in), 14 VCC (power) hidden to VCC
part D pins: 7 GND (power) hidden to GND, 11 (out), 12 (in), 13 (in), 14 VCC (power) hidden to VCC
2 alternate drawings of the same symbol

## SN7409
designator U?
Quad 2-IN Pos And G OCO
footprint DIP-14
footprint SO14
part A pins: 1 (in), 2 (in), 3 (oc), 7 GND (power) hidden to GND, 14 VCC (power) hidden to VCC
part B pins: 4 (in), 5 (in), 6 (oc), 7 GND (power) hidden to GND, 14 VCC (power) hidden to VCC
part C pins: 7 GND (power) hidden to GND, 8 (oc), 9 (in), 10 (in), 14 VCC (power) hidden to VCC
part D pins: 7 GND (power) hidden to GND, 11 (oc), 12 (in), 13 (in), 14 VCC (power) hidden to VCC
2 alternate drawings of the same symbol

## SN7410
designator U?
Triple 3-IN Pos Nand G
footprint DIP-14
footprint SO14
part A pins: 1 (in), 2 (in), 7 GND (power) hidden to GND, 12 (out), 13 (in), 14 VCC (power) hidden to VCC
part B pins: 3 (in), 4 (in), 5 (in), 6 (out), 7 GND (power) hidden to GND, 14 VCC (power) hidden to VCC
part C pins: 7 GND (power) hidden to GND, 8 (out), 9 (in), 10 (in), 11 (in), 14 VCC (power) hidden to VCC
2 alternate drawings of the same symbol

## SN7412
designator U?
Triple 3-IN Pos Nand G OCO
footprint DIP-14
footprint SO14
part A pins: 1 (in), 2 (in), 7 GND (power) hidden to GND, 12 (oc), 13 (in), 14 VCC (power) hidden to VCC
part B pins: 3 (in), 4 (in), 5 (in), 6 (oc), 7 GND (power) hidden to GND, 14 VCC (power) hidden to VCC
part C pins: 7 GND (power) hidden to GND, 8 (oc), 9 (in), 10 (in), 11 (in), 14 VCC (power) hidden to VCC
2 alternate drawings of the same symbol

## SN7414
designator U?
Hex Inverter SCH
footprint DIP-14
footprint SO14
part A pins: 1 (in), 2 (out), 7 GND (power) hidden to GND, 14 VCC (power) hidden to VCC
part B pins: 3 (in), 4 (out), 7 GND (power) hidden to GND, 14 VCC (power) hidden to VCC
part C pins: 5 (in), 6 (out), 7 GND (power) hidden to GND, 14 VCC (power) hidden to VCC
part D pins: 7 GND (power) hidden to GND, 8 (out), 9 (in), 14 VCC (power) hidden to VCC
part E pins: 7 GND (power) hidden to GND, 10 (out), 11 (in), 14 VCC (power) hidden to VCC
part F pins: 7 GND (power) hidden to GND, 12 (out), 13 (in), 14 VCC (power) hidden to VCC
2 alternate drawings of the same symbol

## SN7420
designator U?
Dual 4-IN Pos Nand G
footprint DIP-14
footprint SO14
part A pins: 1 (in), 2 (in), 4 (in), 5 (in), 6 (out), 7 GND (power) hidden to GND, 14 VCC (power) hidden to VCC
part B pins: 7 GND (power) hidden to GND, 8 (out), 9 (in), 10 (in), 12 (in), 13 (in), 14 VCC (power) hidden to VCC
2 alternate drawings of the same symbol

## SN7422
designator U?
Dual 4-IN Pos And G OCO
footprint DIP-14
footprint SO14
part A pins: 1 (in), 2 (in), 4 (in), 5 (in), 6 (oc), 7 GND (power) hidden to GND, 14 VCC (power) hidden to VCC
part B pins: 7 GND (power) hidden to GND, 8 (oc), 9 (in), 10 (in), 12 (in), 13 (in), 14 VCC (power) hidden to VCC
2 alternate drawings of the same symbol

## SN7423
designator U?
Dual 4-in Pos Nor G Strobe
footprint DIP-16
part A pins: 1 X (in), 2 A (in), 3 B (in), 4 G (in), 5 C (in), 6 D (in), 7 Y (out), 8 GND (power) hidden to GND, 15 ~{X} (in), 16 VCC (power) hidden to VCC
part B pins: 8 GND (power) hidden to GND, 9 Y (out), 10 A (in), 11 B (in), 12 G (in), 13 C (in), 14 D (in), 16 VCC (power) hidden to VCC
1 alternate drawing of the same symbol

## SN7425
designator U?
Dual 4-in Pos Nor G Strobe
footprint DIP-14
part A pins: 1 A (in), 2 B (in), 3 G (in), 4 C (in), 5 D (in), 6 Y (out), 7 GND (power) hidden to GND, 14 VCC (power) hidden to VCC
part B pins: 7 GND (power) hidden to GND, 8 Y (out), 9 A (in), 10 B (in), 11 G (in), 12 C (in), 13 D (in), 14 VCC (power) hidden to VCC
1 alternate drawing of the same symbol

## SN7427
designator U?
Triple 3-IN Pos Nor G
footprint DIP-14
footprint SO14
part A pins: 1 (in), 2 (in), 7 GND (power) hidden to GND, 12 (out), 13 (in), 14 VCC (power) hidden to VCC
part B pins: 3 (in), 4 (in), 5 (in), 6 (out), 7 GND (power) hidden to GND, 14 VCC (power) hidden to VCC
part C pins: 7 GND (power) hidden to GND, 8 (out), 9 (in), 10 (in), 11 (in), 14 VCC (power) hidden to VCC
2 alternate drawings of the same symbol

## SN7430
designator U?
8-IN Nand Pos G
footprint DIP-14
footprint SO14
pins: 1 (in), 2 (in), 3 (in), 4 (in), 5 (in), 6 (in), 7 GND (power) hidden to GND, 8 (out), 11 (in), 12 (in), 14 VCC (power) hidden to VCC
2 alternate drawings of the same symbol

## SN7432
designator U?
Quad 2-IN Pos Or G
footprint DIP-14
footprint SO14
part A pins: 1 (in), 2 (in), 3 (out), 7 GND (power) hidden to GND, 14 VCC (power) hidden to VCC
part B pins: 4 (in), 5 (in), 6 (out), 7 GND (power) hidden to GND, 14 VCC (power) hidden to VCC
part C pins: 7 GND (power) hidden to GND, 8 (out), 9 (in), 10 (in), 14 VCC (power) hidden to VCC
part D pins: 7 GND (power) hidden to GND, 11 (out), 12 (in), 13 (in), 14 VCC (power) hidden to VCC
2 alternate drawings of the same symbol

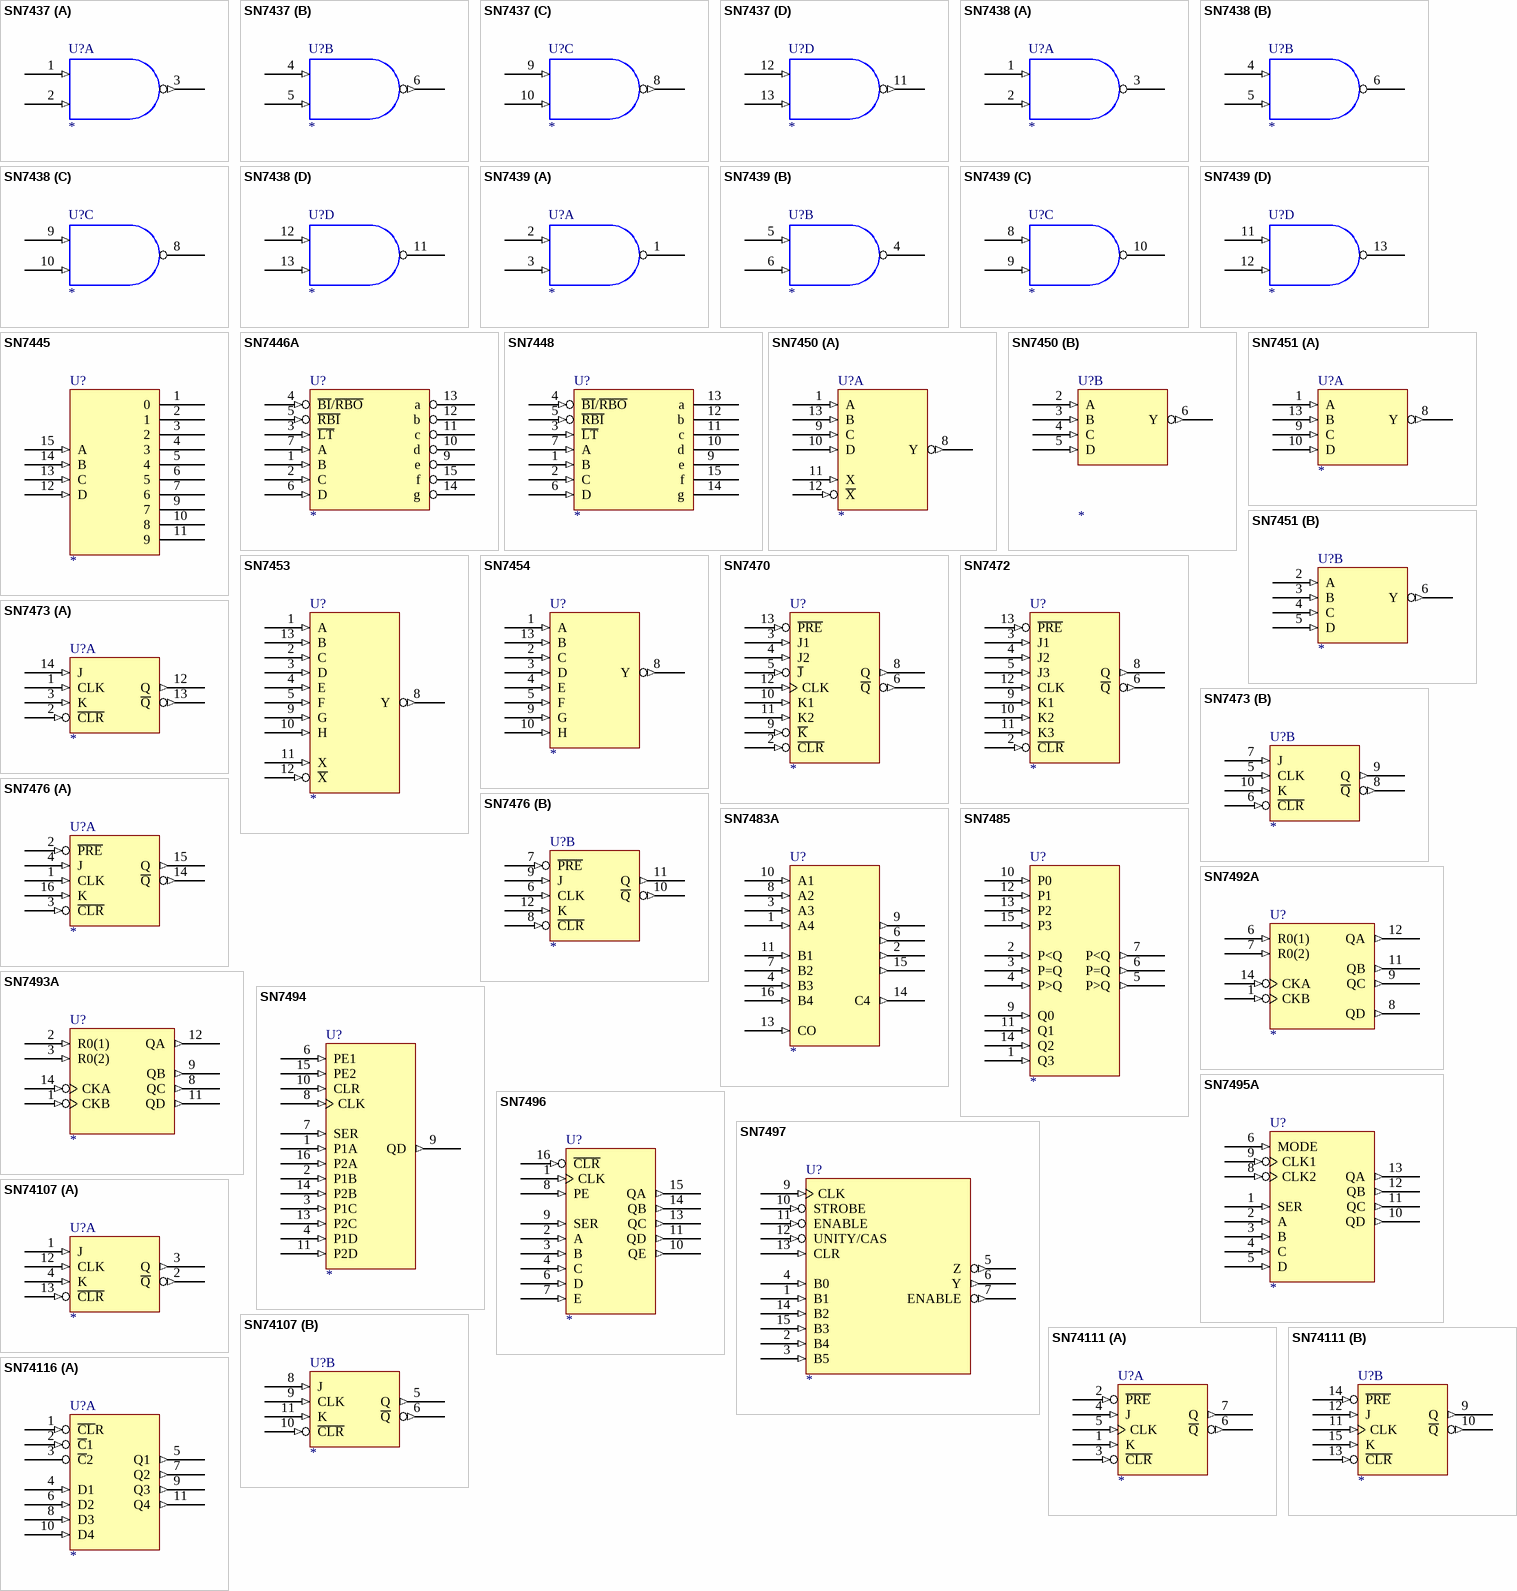
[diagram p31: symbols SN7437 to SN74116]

## SN7437
designator U?
Quad 2-IN Pos Nand G BUF
footprint DIP-14
footprint SO14
part A pins: 1 (in), 2 (in), 3 (out), 7 GND (power) hidden to GND, 14 VCC (power) hidden to VCC
part B pins: 4 (in), 5 (in), 6 (out), 7 GND (power) hidden to GND, 14 VCC (power) hidden to VCC
part C pins: 7 GND (power) hidden to GND, 8 (out), 9 (in), 10 (in), 14 VCC (power) hidden to VCC
part D pins: 7 GND (power) hidden to GND, 11 (out), 12 (in), 13 (in), 14 VCC (power) hidden to VCC
2 alternate drawings of the same symbol

## SN7438
designator U?
Quad 2-IN Pos Nand G BUF OCO
footprint DIP-14
footprint SO14
part A pins: 1 (in), 2 (in), 3 (oc), 7 GND (power) hidden to GND, 14 VCC (power) hidden to VCC
part B pins: 4 (in), 5 (in), 6 (oc), 7 GND (power) hidden to GND, 14 VCC (power) hidden to VCC
part C pins: 7 GND (power) hidden to GND, 8 (oc), 9 (in), 10 (in), 14 VCC (power) hidden to VCC
part D pins: 7 GND (power) hidden to GND, 11 (oc), 12 (in), 13 (in), 14 VCC (power) hidden to VCC
2 alternate drawings of the same symbol

## SN7439
designator U?
Quad 2-IN Pos Nand G BUF OCO
footprint DIP-14
part A pins: 1 (oc), 2 (in), 3 (in), 7 GND (power) hidden to GND, 14 VCC (power) hidden to VCC
part B pins: 4 (oc), 5 (in), 6 (in), 7 GND (power) hidden to GND, 14 VCC (power) hidden to VCC
part C pins: 7 GND (power) hidden to GND, 8 (in), 9 (in), 10 (oc), 14 VCC (power) hidden to VCC
part D pins: 7 GND (power) hidden to GND, 11 (in), 12 (in), 13 (oc), 14 VCC (power) hidden to VCC
2 alternate drawings of the same symbol

## SN7445
designator U?
BCD-To-Decimal DEC DRV
footprint DIP-16
pins: 1 0 (oc), 2 1 (oc), 3 2 (oc), 4 3 (oc), 5 4 (oc), 6 5 (oc), 7 6 (oc), 8 GND (power) hidden to GND, 9 7 (oc), 10 8 (oc), 11 9 (oc), 12 D (in), 13 C (in), 14 B (in), 15 A (in), 16 VCC (power) hidden to VCC
1 alternate drawing of the same symbol

## SN7446A
designator U?
BCD-To-SEVEN-SEGMENT DEC DRV
footprint DIP-16
footprint SO16
pins: 1 B (in), 2 C (in), 3 ~{LT} (in), 4 ~{BI}/~{RBO} (in), 5 ~{RBI} (in), 6 D (in), 7 A (in), 8 GND (power) hidden to GND, 9 e (oc), 10 d (oc), 11 c (oc), 12 b (oc), 13 a (oc), 14 g (oc), 15 f (oc), 16 VCC (power) hidden to VCC
1 alternate drawing of the same symbol

## SN7448
designator U?
BCD-To-SEVEN-SEGMENT DEC DRV
footprint DIP-16
footprint SO16
pins: 1 B (in), 2 C (in), 3 ~{LT} (in), 4 ~{BI}/~{RBO} (in), 5 ~{RBI} (in), 6 D (in), 7 A (in), 8 GND (power) hidden to GND, 9 e (oc), 10 d (oc), 11 c (oc), 12 b (oc), 13 a (oc), 14 g (oc), 15 f (oc), 16 VCC (power) hidden to VCC
1 alternate drawing of the same symbol

## SN7450
designator U?
DUAL 2-WIDE 2-IN AND-OR-INVERT G
footprint DIP-14
part A pins: 1 A (in), 7 GND (power) hidden to GND, 8 Y (out), 9 C (in), 10 D (in), 11 X (in), 12 ~{X} (in), 13 B (in), 14 VCC (power) hidden to VCC
part B pins: 2 A (in), 3 B (in), 4 C (in), 5 D (in), 6 Y (out), 7 GND (power) hidden to GND, 14 VCC (power) hidden to VCC
1 alternate drawing of the same symbol

## SN7451
designator U?
DUAL 2-WIDE 2-IN AND-OR-INVERT G
footprint DIP-14
footprint SO14
part A pins: 1 A (in), 7 GND (power) hidden to GND, 8 Y (out), 9 C (in), 10 D (in), 13 B (in), 14 VCC (power) hidden to VCC
part B pins: 2 A (in), 3 B (in), 4 C (in), 5 D (in), 6 Y (out), 7 GND (power) hidden to GND, 14 VCC (power) hidden to VCC
1 alternate drawing of the same symbol

## SN7453
designator U?
EXPANDABLE 4-WIDE 2-IN AND-OR-INVERT G
footprint DIP-14
pins: 1 A (in), 2 C (in), 3 D (in), 4 E (in), 5 F (in), 7 GND (power) hidden to GND, 8 Y (out), 9 G (in), 10 H (in), 11 X (in), 12 ~{X} (in), 13 B (in), 14 VCC (power) hidden to VCC
1 alternate drawing of the same symbol

## SN7454
designator U?
4-WIDE 2-IN AND-OR-INVERT G
footprint DIP-14
pins: 1 A (in), 2 C (in), 3 D (in), 4 E (in), 5 F (in), 7 GND (power) hidden to GND, 8 Y (out), 9 G (in), 10 H (in), 13 B (in), 14 VCC (power) hidden to VCC
1 alternate drawing of the same symbol

## SN7470
designator U?
AND-GATED J-K PET FF RS CR
footprint DIP-14
pins: 2 ~{CLR} (in), 3 J1 (in), 4 J2 (in), 5 ~{J} (in), 6 ~{Q} (out), 7 GND (power) hidden to GND, 8 Q (out), 9 ~{K} (in), 10 K1 (in), 11 K2 (in), 12 CLK (in), 13 ~{PRE} (in), 14 VCC (power) hidden to VCC
1 alternate drawing of the same symbol

## SN7472
designator U?
AND-GATED J-K ms FF RS CR
footprint DIP-14
pins: 2 ~{CLR} (in), 3 J1 (in), 4 J2 (in), 5 J3 (in), 6 ~{Q} (out), 7 GND (power) hidden to GND, 8 Q (out), 9 K1 (in), 10 K2 (in), 11 K3 (in), 12 CLK (in), 13 ~{PRE} (in), 14 VCC (power) hidden to VCC
1 alternate drawing of the same symbol

## SN7473
designator U?
DUAL J-K FF CR
footprint DIP-14
footprint SO14
part A pins: 1 CLK (in), 2 ~{CLR} (in), 3 K (in), 4 GND (power) hidden to GND, 11 VCC (power) hidden to VCC, 12 Q (out), 13 ~{Q} (out), 14 J (in)
part B pins: 4 GND (power) hidden to GND, 5 CLK (in), 6 ~{CLR} (in), 7 J (in), 8 ~{Q} (out), 9 Q (out), 10 K (in), 11 VCC (power) hidden to VCC
1 alternate drawing of the same symbol

## SN7476
designator U?
DUAL J-K FF RS CR
footprint DIP-16
part A pins: 1 CLK (in), 2 ~{PRE} (in), 3 ~{CLR} (in), 4 J (in), 5 VCC (power) hidden to VCC, 13 GND (power) hidden to GND, 14 ~{Q} (out), 15 Q (out), 16 K (in)
part B pins: 5 VCC (power) hidden to VCC, 6 CLK (in), 7 ~{PRE} (in), 8 ~{CLR} (in), 9 J (in), 10 ~{Q} (out), 11 Q (out), 12 K (in), 13 GND (power) hidden to GND
1 alternate drawing of the same symbol

## SN7483A
designator U?
4-BIT FULL ADD FC
footprint DIP-16
footprint SO16
pins: 1 A4 (in), 2 (out), 3 A3 (in), 4 B3 (in), 5 VCC (power) hidden to VCC, 6 (out), 7 B2 (in), 8 A2 (in), 9 (out), 10 A1 (in), 11 B1 (in), 12 GND (power) hidden to GND, 13 CO (in), 14 C4 (out), 15 (out), 16 B4 (in)
1 alternate drawing of the same symbol

## SN7485
designator U?
4-BIT MAGNITUDE COMP
footprint DIP-16
footprint SO16
pins: 1 Q3 (in), 2 P<Q (in), 3 P=Q (in), 4 P>Q (in), 5 P>Q (out), 6 P=Q (out), 7 P<Q (out), 8 GND (power) hidden to GND, 9 Q0 (in), 10 P0 (in), 11 Q1 (in), 12 P1 (in), 13 P2 (in), 14 Q2 (in), 15 P3 (in), 16 VCC (power) hidden to VCC
1 alternate drawing of the same symbol

## SN7492A
designator U?
DECADE DIV-BY-12 BIN CNT
footprint DIP-14
footprint SO14
pins: 1 CKB (in), 5 VCC (power) hidden to VCC, 6 R0(1) (in), 7 R0(2) (in), 8 QD (out), 9 QC (out), 10 GND (power) hidden to GND, 11 QB (out), 12 QA (out), 14 CKA (in)
1 alternate drawing of the same symbol

## SN7493A
designator U?
DECADE DIV-BY-12 BIN CNT
footprint DIP-14
footprint SO14
pins: 1 CKB (in), 2 R0(1) (in), 3 R0(2) (in), 5 VCC (power) hidden to VCC, 8 QC (out), 9 QB (out), 10 GND (power) hidden to GND, 11 QD (out), 12 QA (out), 14 CKA (in)
1 alternate drawing of the same symbol

## SN7494
designator U?
4-BIT SHIFT REG
footprint DIP-16
pins: 1 P1A (in), 2 P1B (in), 3 P1C (in), 4 P1D (in), 5 VCC (power) hidden to VCC, 6 PE1 (in), 7 SER (in), 8 CLK (in), 9 QD (out), 10 CLR (in), 11 P2D (in), 12 GND (power) hidden to GND, 13 P2C (in), 14 P2B (in), 15 PE2 (in), 16 P2A (in)
1 alternate drawing of the same symbol

## SN7495A
designator U?
4-BIT PA SHIFT REG
footprint DIP-14
footprint SO14
pins: 1 SER (in), 2 A (in), 3 B (in), 4 C (in), 5 D (in), 6 MODE (in), 7 GND (power) hidden to GND, 8 CLK2 (in), 9 CLK1 (in), 10 QD (out), 11 QC (out), 12 QB (out), 13 QA (out), 14 VCC (power) hidden to VCC
1 alternate drawing of the same symbol

## SN7496
designator U?
5-BIT SHIFT REG
footprint DIP-16
footprint SO16
pins: 1 CLK (in), 2 A (in), 3 B (in), 4 C (in), 5 VCC (power) hidden to VCC, 6 D (in), 7 E (in), 8 PE (in), 9 SER (in), 10 QE (out), 11 QD (out), 12 GND (power) hidden to GND, 13 QC (out), 14 QB (out), 15 QA (out), 16 ~{CLR} (in)
1 alternate drawing of the same symbol

## SN7497
designator U?
SYN 6-BIT BIN RATE MULT
footprint DIP-16
pins: 1 B1 (in), 2 B4 (in), 3 B5 (in), 4 B0 (in), 5 Z (out), 6 Y (out), 7 ENABLE (out), 8 GND (power) hidden to GND, 9 CLK (in), 10 STROBE (in), 11 ENABLE (in), 12 UNITY/CAS (in), 13 CLR (in), 14 B2 (in), 15 B3 (in), 16 VCC (power) hidden to VCC
1 alternate drawing of the same symbol

## SN74107
designator U?
DUAL J-K FF CR
footprint DIP-14
part A pins: 1 J (in), 2 ~{Q} (out), 3 Q (out), 4 K (in), 7 GND (power) hidden to GND, 12 CLK (in), 13 ~{CLR} (in), 14 VCC (power) hidden to VCC
part B pins: 5 Q (out), 6 ~{Q} (out), 7 GND (power) hidden to GND, 8 J (in), 9 CLK (in), 10 ~{CLR} (in), 11 K (in), 14 VCC (power) hidden to VCC
1 alternate drawing of the same symbol

## SN74111
designator U?
DUAL J-K MS DATA LOCKOUT
footprint DIP-16
part A pins: 1 K (in), 2 ~{PRE} (in), 3 ~{CLR} (in), 4 J (in), 5 CLK (in), 6 ~{Q} (out), 7 Q (out), 8 GND (power) hidden to GND, 16 VCC (power) hidden to VCC
part B pins: 8 GND (power) hidden to GND, 9 Q (out), 10 ~{Q} (out), 11 CLK (in), 12 J (in), 13 ~{CLR} (in), 14 ~{PRE} (in), 15 K (in), 16 VCC (power) hidden to VCC
1 alternate drawing of the same symbol

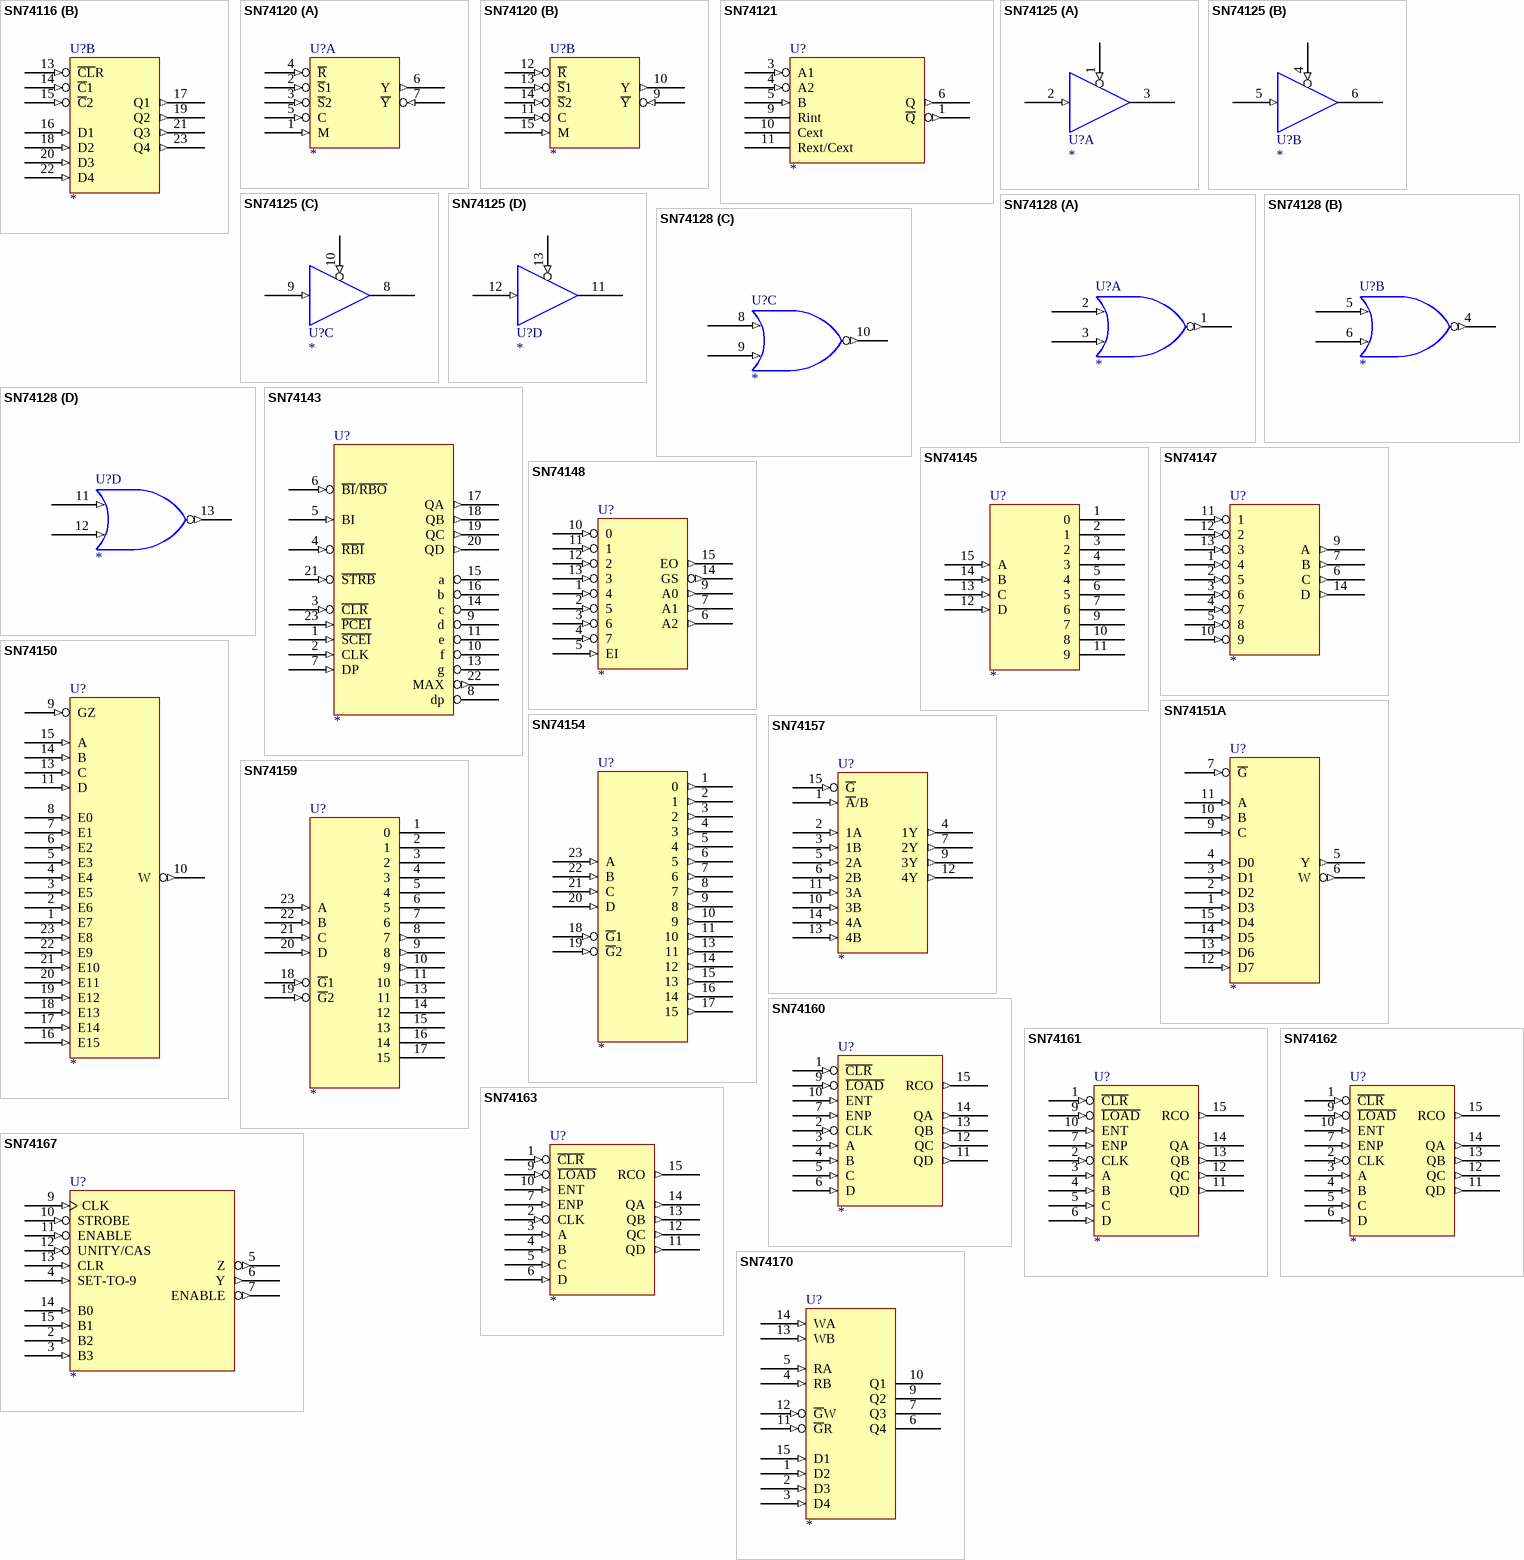
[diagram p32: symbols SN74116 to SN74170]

## SN74116
designator U?
DUAL 4-BIT LCH CR
footprint DIP-24
part A pins: 1 ~{CL}R (in), 2 ~{C}1 (in), 3 ~{C}2, 4 D1 (in), 5 Q1 (out), 6 D2 (in), 7 Q2 (out), 8 D3 (in), 9 Q3 (out), 10 D4 (in), 11 Q4 (out), 12 GND (power) hidden to GND, 24 VCC (power) hidden to VCC
part B pins: 12 GND (power) hidden to GND, 13 ~{CL}R (in), 14 ~{C}1 (in), 15 ~{C}2 (in), 16 D1 (in), 17 Q1 (out), 18 D2 (in), 19 Q2 (out), 20 D3 (in), 21 Q3 (out), 22 D4 (in), 23 Q4 (out), 24 VCC (power) hidden to VCC
1 alternate drawing of the same symbol

## SN74120
designator U?
DUAL PULSE SYNR DRV
footprint DIP-16
part A pins: 1 M (in), 2 ~{S}1 (in), 3 ~{S}2 (in), 4 ~{R} (in), 5 C (in), 6 Y (out), 7 ~{Y} (in), 8 GND (power) hidden to GND, 16 VCC (power) hidden to VCC
part B pins: 8 GND (power) hidden to GND, 9 ~{Y} (in), 10 Y (out), 11 C (in), 12 ~{R} (in), 13 ~{S}1 (in), 14 ~{S}2 (in), 15 M (in), 16 VCC (power) hidden to VCC
1 alternate drawing of the same symbol

## SN74121
designator U?
MONOSTABLE MULTIVIBRATOR SCHI
footprint DIP-14
pins: 1 ~{Q} (out), 3 A1 (in), 4 A2 (in), 5 B (in), 6 Q (out), 7 GND (power) hidden to GND, 9 Rint, 10 Cext, 11 Rext/Cext, 14 VCC (power) hidden to VCC
1 alternate drawing of the same symbol

## SN74125
designator U?
QUAD BUS BUF 3SO
footprint DIP-14
part A pins: 1 (in), 2 (in), 3 (hiz), 7 GND (power) hidden to GND, 14 VCC (power) hidden to VCC
part B pins: 4 (in), 5 (in), 6 (hiz), 7 GND (power) hidden to GND, 14 VCC (power) hidden to VCC
part C pins: 7 GND (power) hidden to GND, 8 (hiz), 9 (in), 10 (in), 14 VCC (power) hidden to VCC
part D pins: 7 GND (power) hidden to GND, 11 (hiz), 12 (in), 13 (in), 14 VCC (power) hidden to VCC
2 alternate drawings of the same symbol

## SN74128
designator U?
QUAD LINE DRV
footprint DIP-14
part A pins: 1 (out), 2 (in), 3 (in), 7 GND (power) hidden to GND, 14 VCC (power) hidden to VCC
part B pins: 4 (out), 5 (in), 6 (in), 7 GND (power) hidden to GND, 14 VCC (power) hidden to VCC
part C pins: 7 GND (power) hidden to GND, 8 (in), 9 (in), 10 (out), 14 VCC (power) hidden to VCC
part D pins: 7 GND (power) hidden to GND, 11 (in), 12 (in), 13 (out), 14 VCC (power) hidden to VCC
2 alternate drawings of the same symbol

## SN74143
designator U?
4-BIT CNT/LCH SEVEN SEG LED/LAMP DRV
footprint DIP-24
pins: 1 ~{SCEI} (in), 2 CLK (in), 3 ~{CLR} (in), 4 ~{RBI} (in), 5 BI (in), 6 ~{BI}/~{RBO} (in), 7 DP (in), 8 dp (oc), 9 d (oc), 10 f (oc), 11 e (oc), 12 GND (power) hidden to GND, 13 g (oc), 14 c (oc), 15 a (oc), 16 b (oc), 17 QA (out), 18 QB (out), 19 QC (out), 20 QD (out), 21 ~{STRB} (in), 22 MAX (out), 23 ~{PCEI} (in), 24 VCC (power) hidden to VCC
1 alternate drawing of the same symbol

## SN74145
designator U?
BCD-To-Decimal DEC DRV
footprint DIP-16
pins: 1 0 (oc), 2 1 (oc), 3 2 (oc), 4 3 (oc), 5 4 (oc), 6 5 (oc), 7 6 (oc), 8 GND (power) hidden to GND, 9 7 (oc), 10 8 (oc), 11 9 (oc), 12 D (in), 13 C (in), 14 B (in), 15 A (in), 16 VCC (power) hidden to VCC
1 alternate drawing of the same symbol

## SN74147
designator U?
10-4 LINE PRIORITY ENC
footprint DIP-16
footprint SO16
pins: 1 4 (in), 2 5 (in), 3 6 (in), 4 7 (in), 5 8 (in), 6 C (out), 7 B (out), 8 GND (power) hidden to GND, 9 A (out), 10 9 (in), 11 1 (in), 12 2 (in), 13 3 (in), 14 D (out), 16 VCC (power) hidden to VCC
1 alternate drawing of the same symbol

## SN74148
designator U?
8-3 LINE PRIORITY ENC
footprint DIP-16
footprint SO16
pins: 1 4 (in), 2 5 (in), 3 6 (in), 4 7 (in), 5 EI (in), 6 A2 (out), 7 A1 (out), 8 GND (power) hidden to GND, 9 A0 (out), 10 0 (in), 11 1 (in), 12 2 (in), 13 3 (in), 14 GS (out), 15 EO (out), 16 VCC (power) hidden to VCC
1 alternate drawing of the same symbol

## SN74150
designator U?
DATA SELEC/MUX
footprint DIP-24
pins: 1 E7 (in), 2 E6 (in), 3 E5 (in), 4 E4 (in), 5 E3 (in), 6 E2 (in), 7 E1 (in), 8 E0 (in), 9 GZ (in), 10 W (out), 11 D (in), 12 GND (power) hidden to GND, 13 C (in), 14 B (in), 15 A (in), 16 E15 (in), 17 E14 (in), 18 E13 (in), 19 E12 (in), 20 E11 (in), 21 E10 (in), 22 E9 (in), 23 E8 (in), 24 VCC (power) hidden to VCC
1 alternate drawing of the same symbol

## SN74151A
designator U?
DATA SELEC/MUX
footprint DIP-16
footprint SO16
pins: 1 D3 (in), 2 D2 (in), 3 D1 (in), 4 D0 (in), 5 Y (out), 6 W (out), 7 ~{G} (in), 8 GND (power) hidden to GND, 9 C (in), 10 B (in), 11 A (in), 12 D7 (in), 13 D6 (in), 14 D5 (in), 15 D4 (in), 16 VCC (power) hidden to VCC
1 alternate drawing of the same symbol

## SN74154
designator U?
4-16LINE DEC DEMUL
footprint DIP-24
pins: 1 0 (out), 2 1 (out), 3 2 (out), 4 3 (out), 5 4 (out), 6 5 (out), 7 6 (out), 8 7 (out), 9 8 (out), 10 9 (out), 11 10 (out), 12 GND (power) hidden to GND, 13 11 (out), 14 12 (out), 15 13 (out), 16 14 (out), 17 15 (out), 18 ~{G}1 (in), 19 ~{G}2 (in), 20 D (in), 21 C (in), 22 B (in), 23 A (in), 24 VCC (power) hidden to VCC
1 alternate drawing of the same symbol

## SN74157
designator U?
QUAD 2-1LINE DATA SELEC/MUX
footprint DIP-16
footprint SO16
pins: 1 ~{A}/B (in), 2 1A (in), 3 1B (in), 4 1Y (out), 5 2A (in), 6 2B (in), 7 2Y (out), 8 GND (power) hidden to GND, 9 3Y (out), 10 3B (in), 11 3A (in), 12 4Y (out), 13 4B (in), 14 4A (in), 15 ~{G} (in), 16 VCC (power) hidden to VCC
1 alternate drawing of the same symbol

## SN74159
designator U?
4-16LINE DEC DEMUL OCO
footprint DIP-24
pins: 1 0 (oc), 2 1 (oc), 3 2 (oc), 4 3 (oc), 5 4 (oc), 6 5 (oc), 7 6 (oc), 8 7 (out), 9 8 (out), 10 9 (out), 11 10 (out), 12 GND (power) hidden to GND, 13 11 (oc), 14 12 (oc), 15 13 (oc), 16 14 (oc), 17 15 (oc), 18 ~{G}1 (in), 19 ~{G}2 (in), 20 D (in), 21 C (in), 22 B (in), 23 A (in), 24 VCC (power) hidden to VCC
1 alternate drawing of the same symbol

## SN74160
designator U?
SYN 4-BIT CNT
footprint DIP-16
pins: 1 ~{CLR} (in), 2 CLK (in), 3 A (in), 4 B (in), 5 C (in), 6 D (in), 7 ENP (in), 8 GND (power) hidden to GND, 9 ~{LOAD} (in), 10 ENT (in), 11 QD (out), 12 QC (out), 13 QB (out), 14 QA (out), 15 RCO (out), 16 VCC (power) hidden to VCC
1 alternate drawing of the same symbol

## SN74161
designator U?
SYN 4-BIT CNT
footprint DIP-16
pins: 1 ~{CLR} (in), 2 CLK (in), 3 A (in), 4 B (in), 5 C (in), 6 D (in), 7 ENP (in), 8 GND (power) hidden to GND, 9 ~{LOAD} (in), 10 ENT (in), 11 QD (out), 12 QC (out), 13 QB (out), 14 QA (out), 15 RCO (out), 16 VCC (power) hidden to VCC
1 alternate drawing of the same symbol

## SN74162
designator U?
SYN 4-BIT CNT
footprint DIP-16
pins: 1 ~{CLR} (in), 2 CLK (in), 3 A (in), 4 B (in), 5 C (in), 6 D (in), 7 ENP (in), 8 GND (power) hidden to GND, 9 ~{LOAD} (in), 10 ENT (in), 11 QD (out), 12 QC (out), 13 QB (out), 14 QA (out), 15 RCO (out), 16 VCC (power) hidden to VCC
1 alternate drawing of the same symbol

## SN74163
designator U?
SYN 4-BIT CNT
footprint DIP-16
pins: 1 ~{CLR} (in), 2 CLK (in), 3 A (in), 4 B (in), 5 C (in), 6 D (in), 7 ENP (in), 8 GND (power) hidden to GND, 9 ~{LOAD} (in), 10 ENT (in), 11 QD (out), 12 QC (out), 13 QB (out), 14 QA (out), 15 RCO (out), 16 VCC (power) hidden to VCC
1 alternate drawing of the same symbol

## SN74167
designator U?
SYN DECADE RATE MULTIPLIERS
footprint DIP-16
pins: 2 B2 (in), 3 B3 (in), 4 SET-TO-9 (in), 5 Z (out), 6 Y (out), 7 ENABLE (out), 8 GND (power) hidden to GND, 9 CLK (in), 10 STROBE (in), 11 ENABLE (in), 12 UNITY/CAS (in), 13 CLR (in), 14 B0 (in), 15 B1 (in), 16 VCC (power) hidden to VCC
1 alternate drawing of the same symbol

## SN74170
designator U?
4-4 REG FILES OCO
footprint DIP-16
footprint SO16
pins: 1 D2 (in), 2 D3 (in), 3 D4 (in), 4 RB (in), 5 RA (in), 6 Q4 (oc), 7 Q3 (oc), 8 GND (power) hidden to GND, 9 Q2 (oc), 10 Q1 (oc), 11 ~{G}R (in), 12 ~{G}W (in), 13 WB (in), 14 WA (in), 15 D1 (in), 16 VCC (power) hidden to VCC
1 alternate drawing of the same symbol

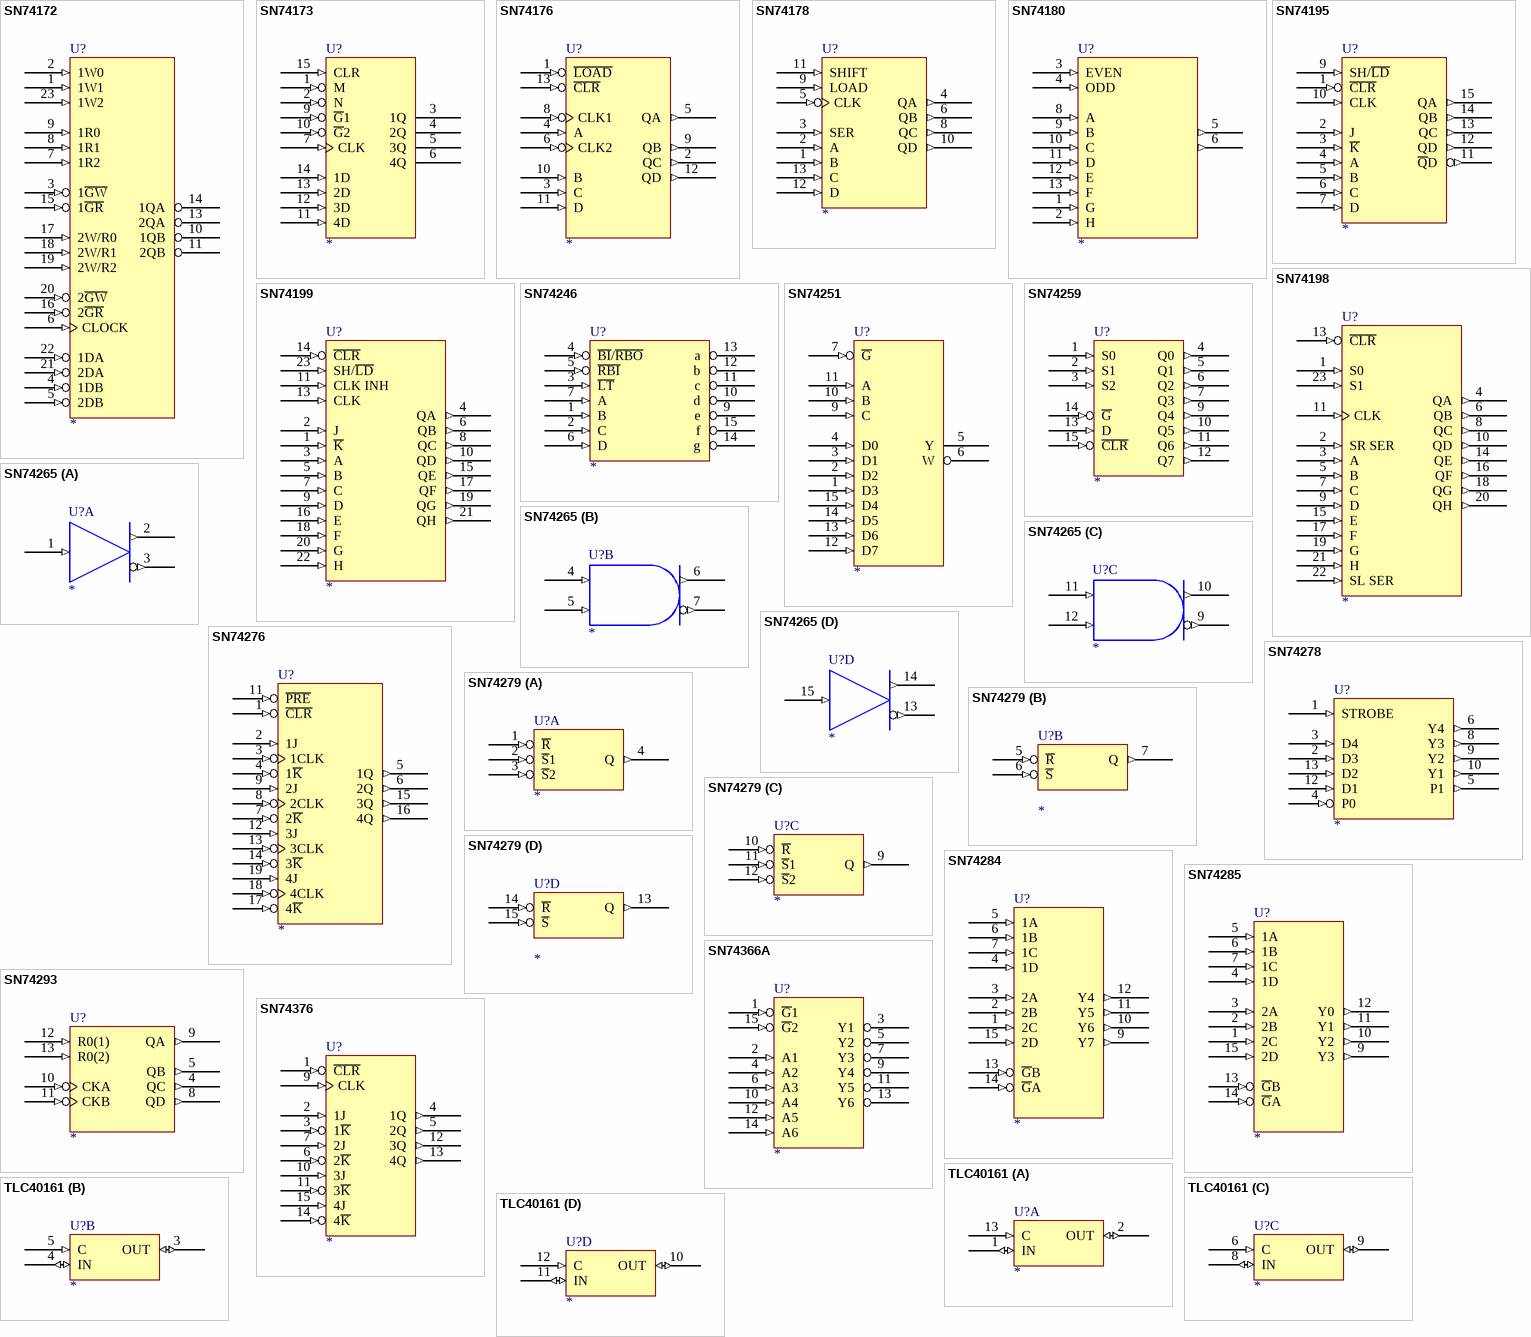
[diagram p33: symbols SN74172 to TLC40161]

## SN74172
designator U?
16-bit multiple-port reg file 3so
footprint DIP-24
pins: 1 1W1 (in), 2 1W0 (in), 3 1~{GW} (in), 4 1DB (in), 5 2DB (in), 6 CLOCK (in), 7 1R2 (in), 8 1R1 (in), 9 1R0 (in), 10 1QB (hiz), 11 2QB (hiz), 12 GND (power) hidden to GND, 13 2QA (hiz), 14 1QA (hiz), 15 1~{GR} (in), 16 2~{GR} (in), 17 2W/R0 (in), 18 2W/R1 (in), 19 2W/R2 (in), 20 2~{GW} (in), 21 2DA (in), 22 1DA (in), 23 1W2 (in), 24 VCC (power) hidden to VCC
1 alternate drawing of the same symbol

## SN74173
designator U?
4-BIT D-TYPE REG 3SO
footprint DIP-16
pins: 1 M (in), 2 N (in), 3 1Q (hiz), 4 2Q (hiz), 5 3Q (hiz), 6 4Q (hiz), 7 CLK (in), 8 GND (power) hidden to GND, 9 ~{G}1 (in), 10 ~{G}2 (in), 11 4D (in), 12 3D (in), 13 2D (in), 14 1D (in), 15 CLR (in), 16 VCC (power) hidden to VCC
1 alternate drawing of the same symbol

## SN74176
designator U?
35-MHZ DECADE BIN CNT/LCH RS
footprint DIP-14
pins: 1 ~{LOAD} (in), 2 QC (out), 3 C (in), 4 A (in), 5 QA (out), 6 CLK2 (in), 7 GND (power) hidden to GND, 8 CLK1 (in), 9 QB (out), 10 B (in), 11 D (in), 12 QD (out), 13 ~{CLR} (in), 14 VCC (power) hidden to VCC
1 alternate drawing of the same symbol

## SN74178
designator U?
4-BIT PARALLEL-ACCESS SFT REG
footprint DIP-14
pins: 1 B (in), 2 A (in), 3 SER (in), 4 QA (out), 5 CLK (in), 6 QB (out), 7 GND (power) hidden to GND, 8 QC (out), 9 LOAD (in), 10 QD (out), 11 SHIFT (in), 12 D (in), 13 C (in), 14 VCC (power) hidden to VCC
1 alternate drawing of the same symbol

## SN74180
designator U?
9-BIT PARITY GNR/CHKR
footprint DIP-14
pins: 1 G (in), 2 H (in), 3 EVEN (in), 4 ODD (in), 5 (out), 6 (out), 7 GND (power) hidden to GND, 8 A (in), 9 B (in), 10 C (in), 11 D (in), 12 E (in), 13 F (in), 14 VCC (power) hidden to VCC
1 alternate drawing of the same symbol

## SN74195
designator U?
4-BIT PARALLEL ACCESS SFT REG
footprint DIP-16
pins: 1 ~{CLR} (in), 2 J (in), 3 ~{K} (in), 4 A (in), 5 B (in), 6 C (in), 7 D (in), 8 GND (power) hidden to GND, 9 SH/~{LD} (in), 10 CLK (in), 11 ~{Q}D (out), 12 QD (out), 13 QC (out), 14 QB (out), 15 QA (out), 16 VCC (power) hidden to VCC
1 alternate drawing of the same symbol

## SN74198
designator U?
8-BIT SFT REG
footprint DIP-24
pins: 1 S0 (in), 2 SR SER (in), 3 A (in), 4 QA (out), 5 B (in), 6 QB (out), 7 C (in), 8 QC (out), 9 D (in), 10 QD (out), 11 CLK (in), 12 GND (power) hidden to GND, 13 ~{CLR} (in), 14 QE (out), 15 E (in), 16 QF (out), 17 F (in), 18 QG (out), 19 G (in), 20 QH (out), 21 H (in), 22 SL SER (in), 23 S1 (in), 24 VCC (power) hidden to VCC
1 alternate drawing of the same symbol

## SN74199
designator U?
8-BIT SFT REG
footprint DIP-24
pins: 1 ~{K} (in), 2 J (in), 3 A (in), 4 QA (out), 5 B (in), 6 QB (out), 7 C (in), 8 QC (out), 9 D (in), 10 QD (out), 11 CLK INH (in), 12 GND (power) hidden to GND, 13 CLK (in), 14 ~{CLR} (in), 15 QE (out), 16 E (in), 17 QF (out), 18 F (in), 19 QG (out), 20 G (in), 21 QH (out), 22 H (in), 23 SH/~{LD} (in), 24 VCC (power) hidden to VCC
1 alternate drawing of the same symbol

## SN74246
designator U?
BCD-TO-SEVEN-SEGMENTDEC/DRV
footprint DIP-16
footprint SO16
pins: 1 B (in), 2 C (in), 3 ~{LT} (in), 4 ~{BI}/~{RBO} (in), 5 ~{RBI} (in), 6 D (in), 7 A (in), 8 GND (power) hidden to GND, 9 e (oc), 10 d (oc), 11 c (oc), 12 b (oc), 13 a (oc), 14 g (oc), 15 f (oc), 16 VCC (power) hidden to VCC
1 alternate drawing of the same symbol

## SN74251
designator U?
DATA SLCR/MUX 3SO
footprint DIP-16
footprint SO16
pins: 1 D3 (in), 2 D2 (in), 3 D1 (in), 4 D0 (in), 5 Y (hiz), 6 W (hiz), 7 ~{G} (in), 8 GND (power) hidden to GND, 9 C (in), 10 B (in), 11 A (in), 12 D7 (in), 13 D6 (in), 14 D5 (in), 15 D4 (in), 16 VCC (power) hidden to VCC
1 alternate drawing of the same symbol

## SN74259
designator U?
8-BIT ADDRESSABLE LCH
footprint DIP-16
footprint SO16
pins: 1 S0 (in), 2 S1 (in), 3 S2 (in), 4 Q0 (out), 5 Q1 (out), 6 Q2 (out), 7 Q3 (out), 8 GND (power) hidden to GND, 9 Q4 (out), 10 Q5 (out), 11 Q6 (out), 12 Q7 (out), 13 D (in), 14 ~{G} (in), 15 ~{CLR} (in), 16 VCC (power) hidden to VCC
1 alternate drawing of the same symbol

## SN74265
designator U?
QUAD COMPLEMENTARY-OUTPUT ELEMENTS
footprint DIP-16
part A pins: 1 (in), 2 (out), 3 (out), 8 GND (power) hidden to GND, 16 VCC (power) hidden to VCC
part B pins: 4 (in), 5 (in), 6 (out), 7 (out), 8 GND (power) hidden to GND, 16 VCC (power) hidden to VCC
part C pins: 8 GND (power) hidden to GND, 9 (out), 10 (out), 11 (in), 12 (in), 16 VCC (power) hidden to VCC
part D pins: 8 GND (power) hidden to GND, 13 (out), 14 (out), 15 (in), 16 VCC (power) hidden to VCC
2 alternate drawings of the same symbol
